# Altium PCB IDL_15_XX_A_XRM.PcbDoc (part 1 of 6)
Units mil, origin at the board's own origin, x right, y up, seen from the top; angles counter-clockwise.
Board outline 6653.34 x 6653.34 mil, 6 copper layers (Top Layer - SIG1, Layer 2 - GND1, Layer 3 - PWR, Layer 4 - PWR, Layer 5 - GND2, Bottom Layer - SIG4), stack 59.843 mil thick; 613 components, 324 nets, 1673 pads, 2316 vias.
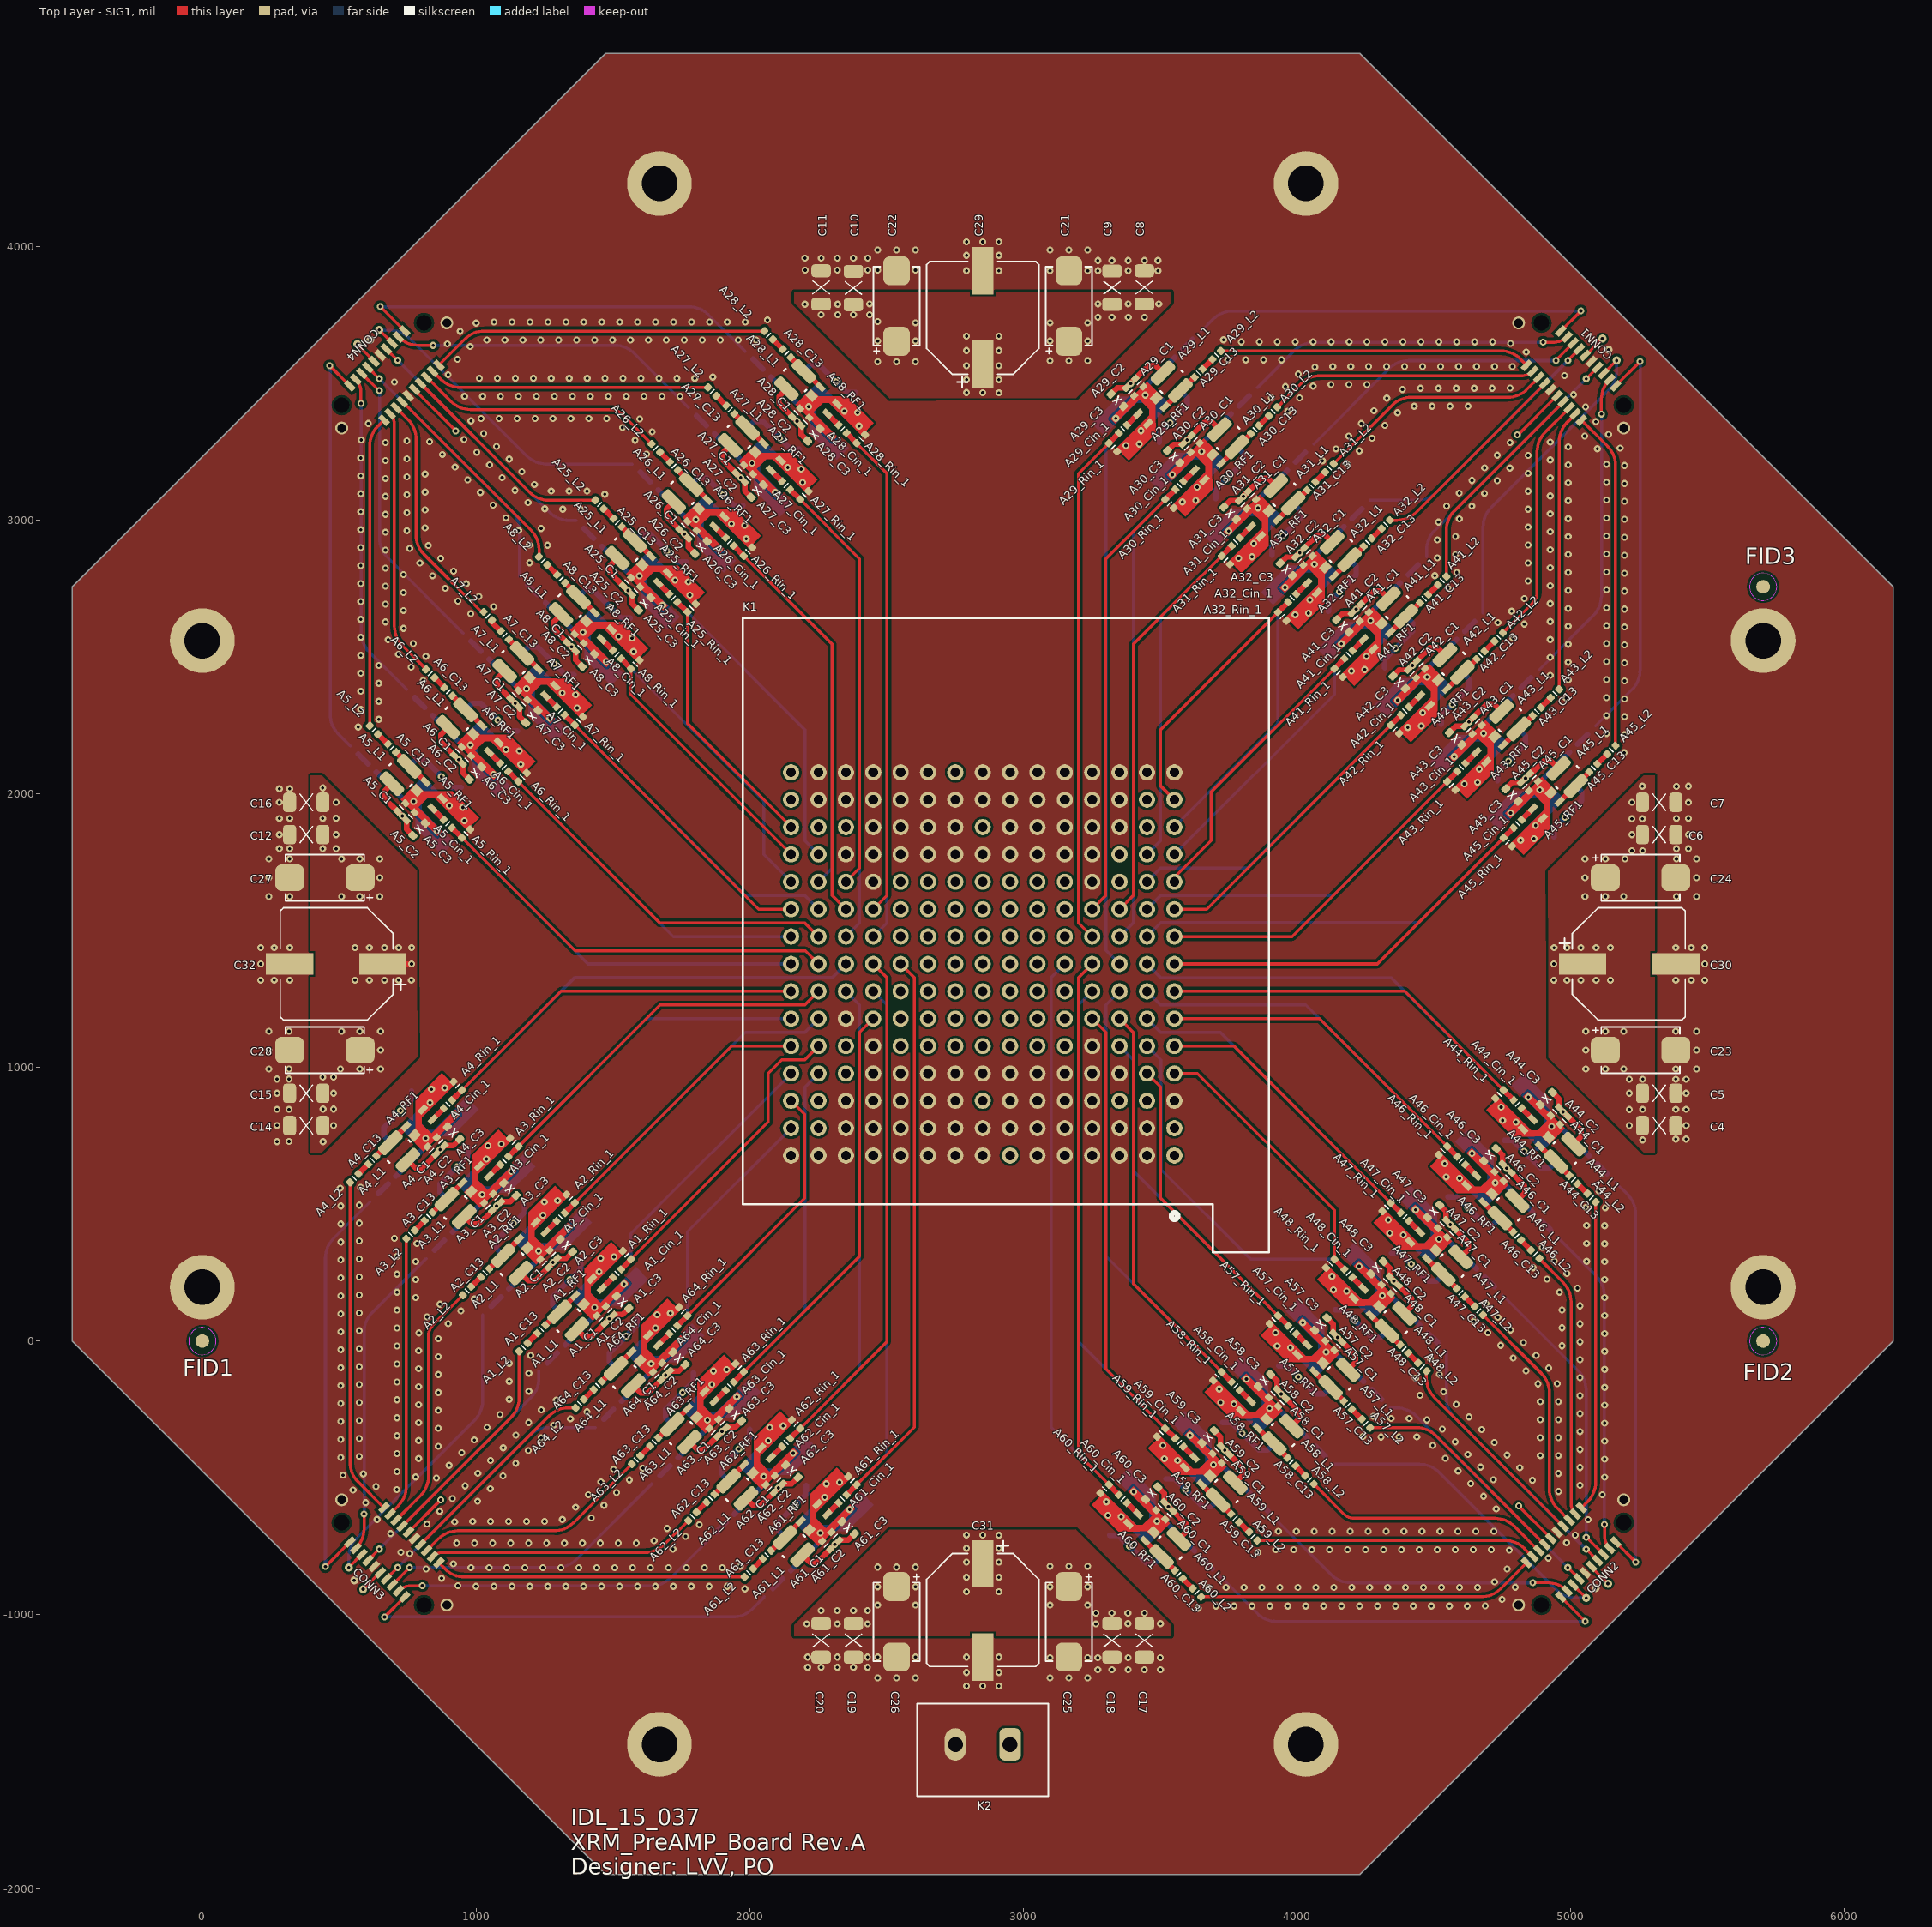
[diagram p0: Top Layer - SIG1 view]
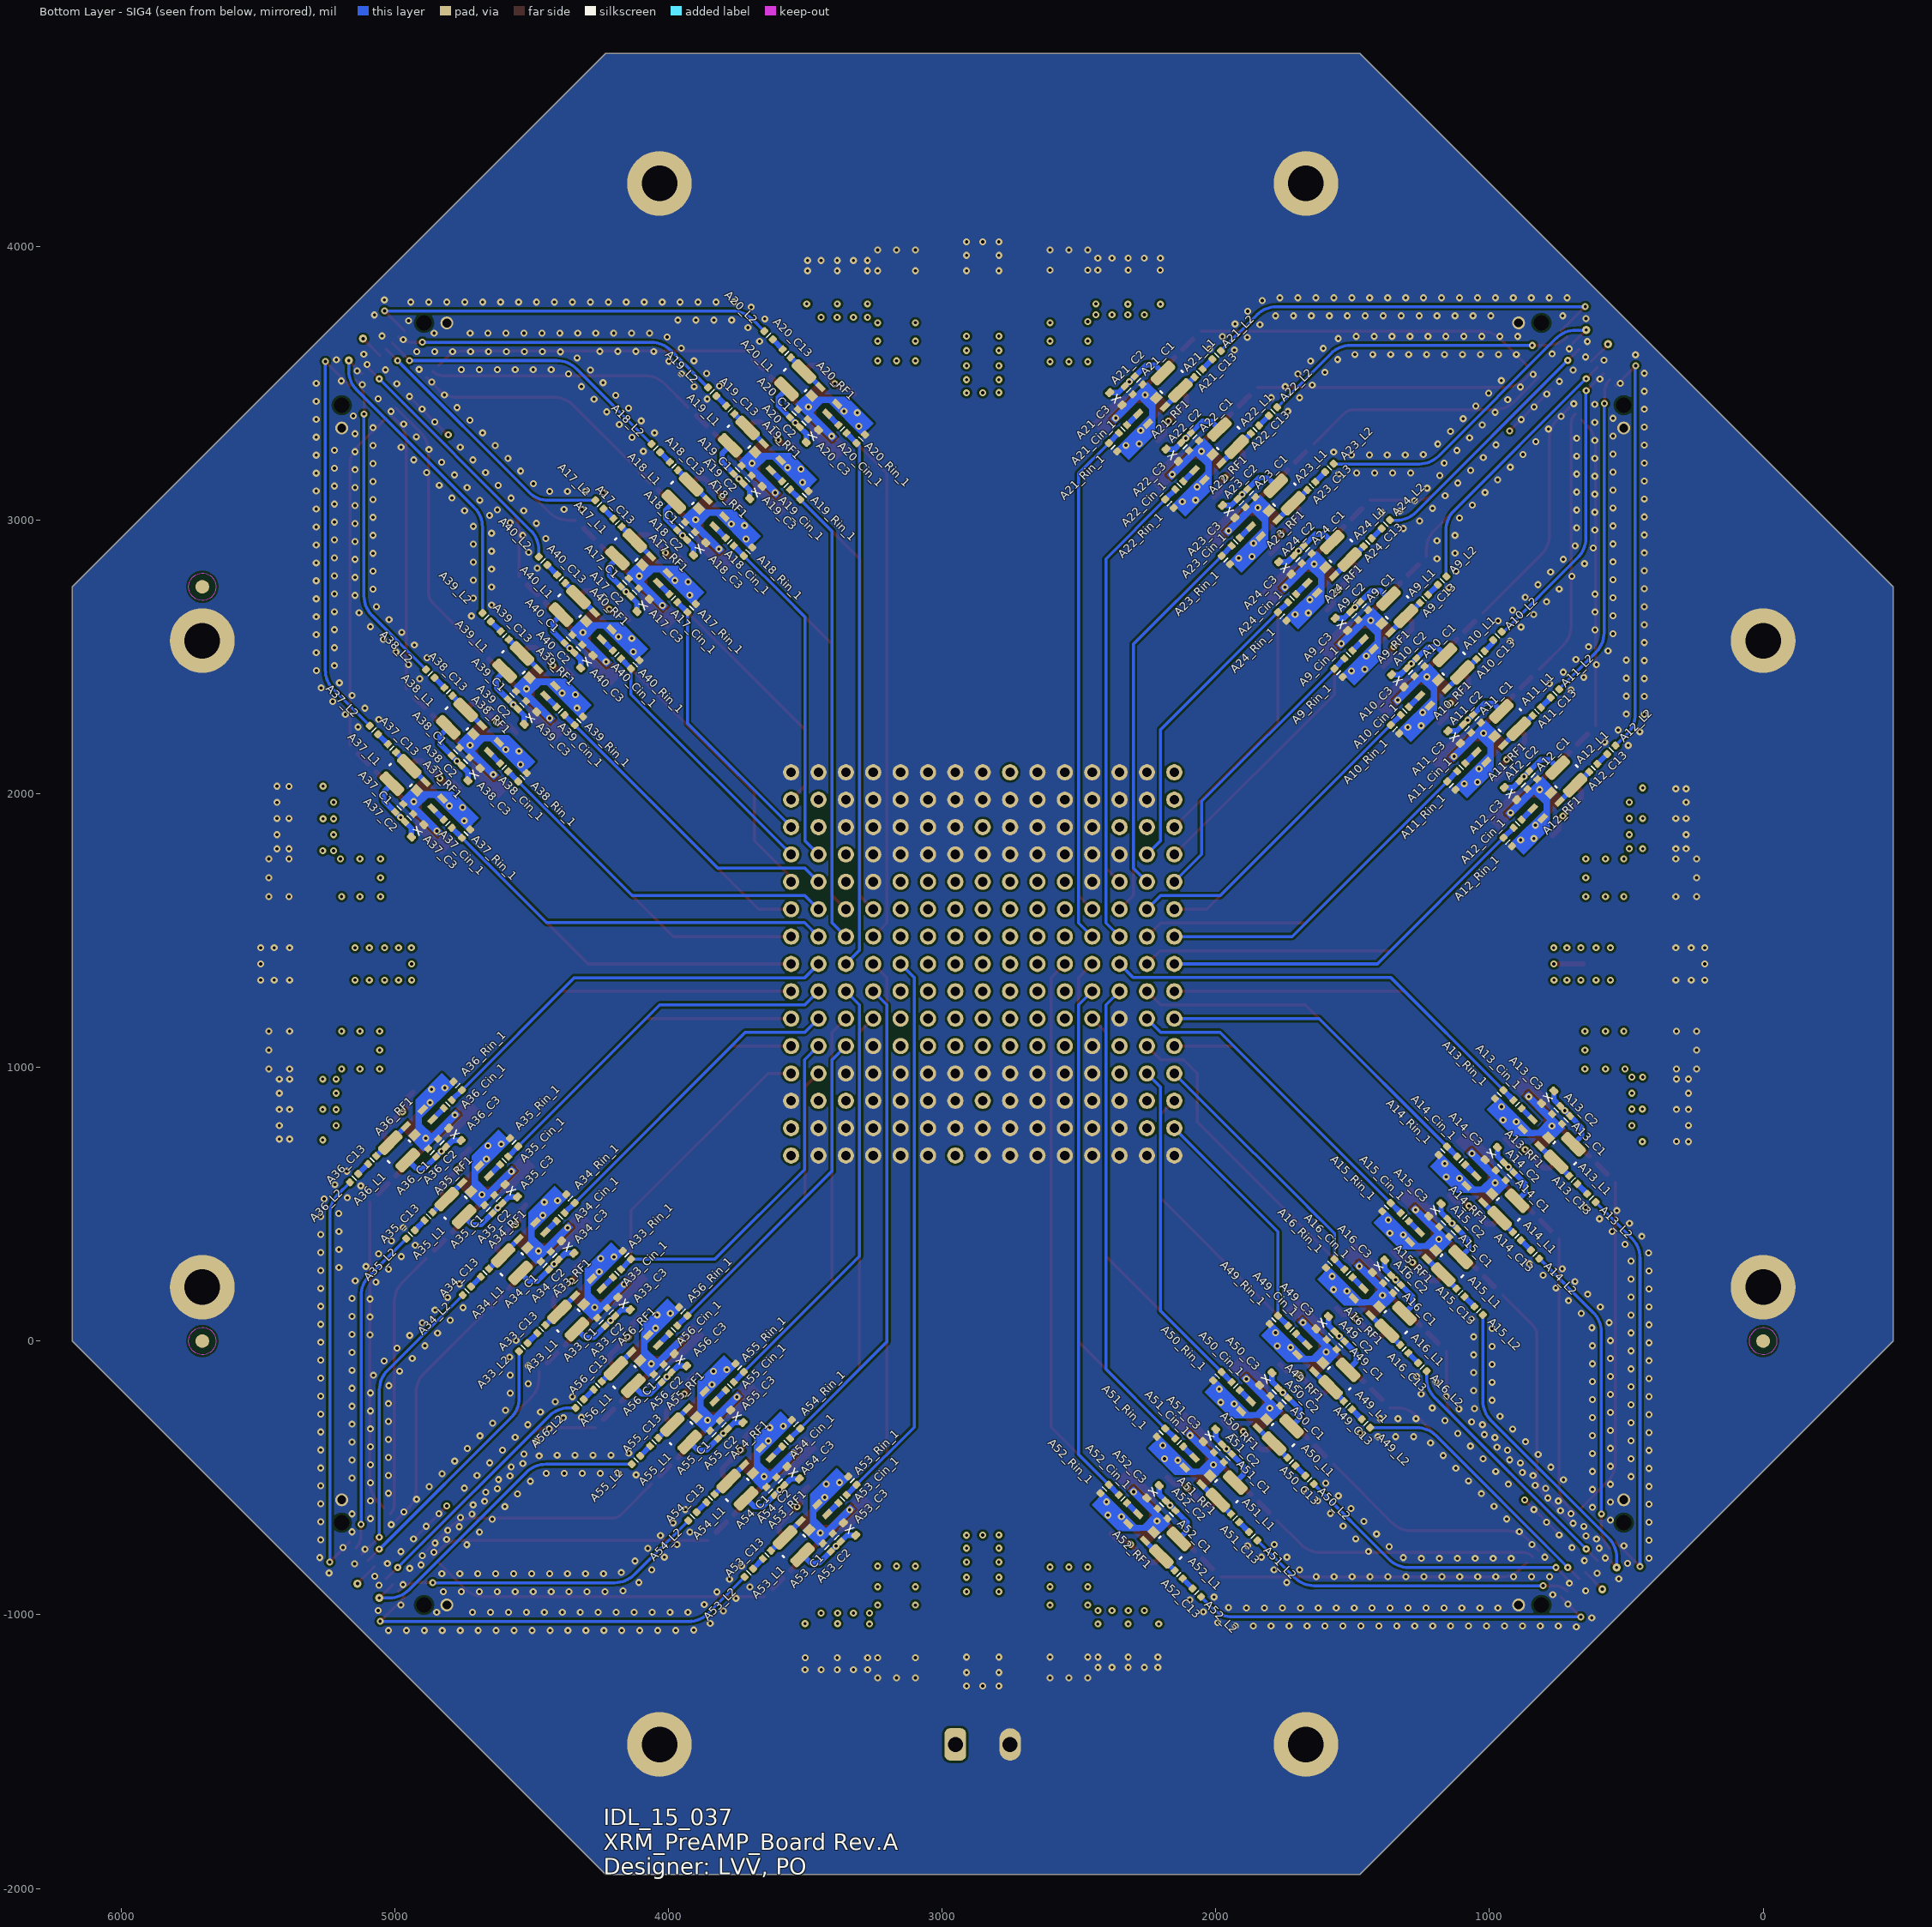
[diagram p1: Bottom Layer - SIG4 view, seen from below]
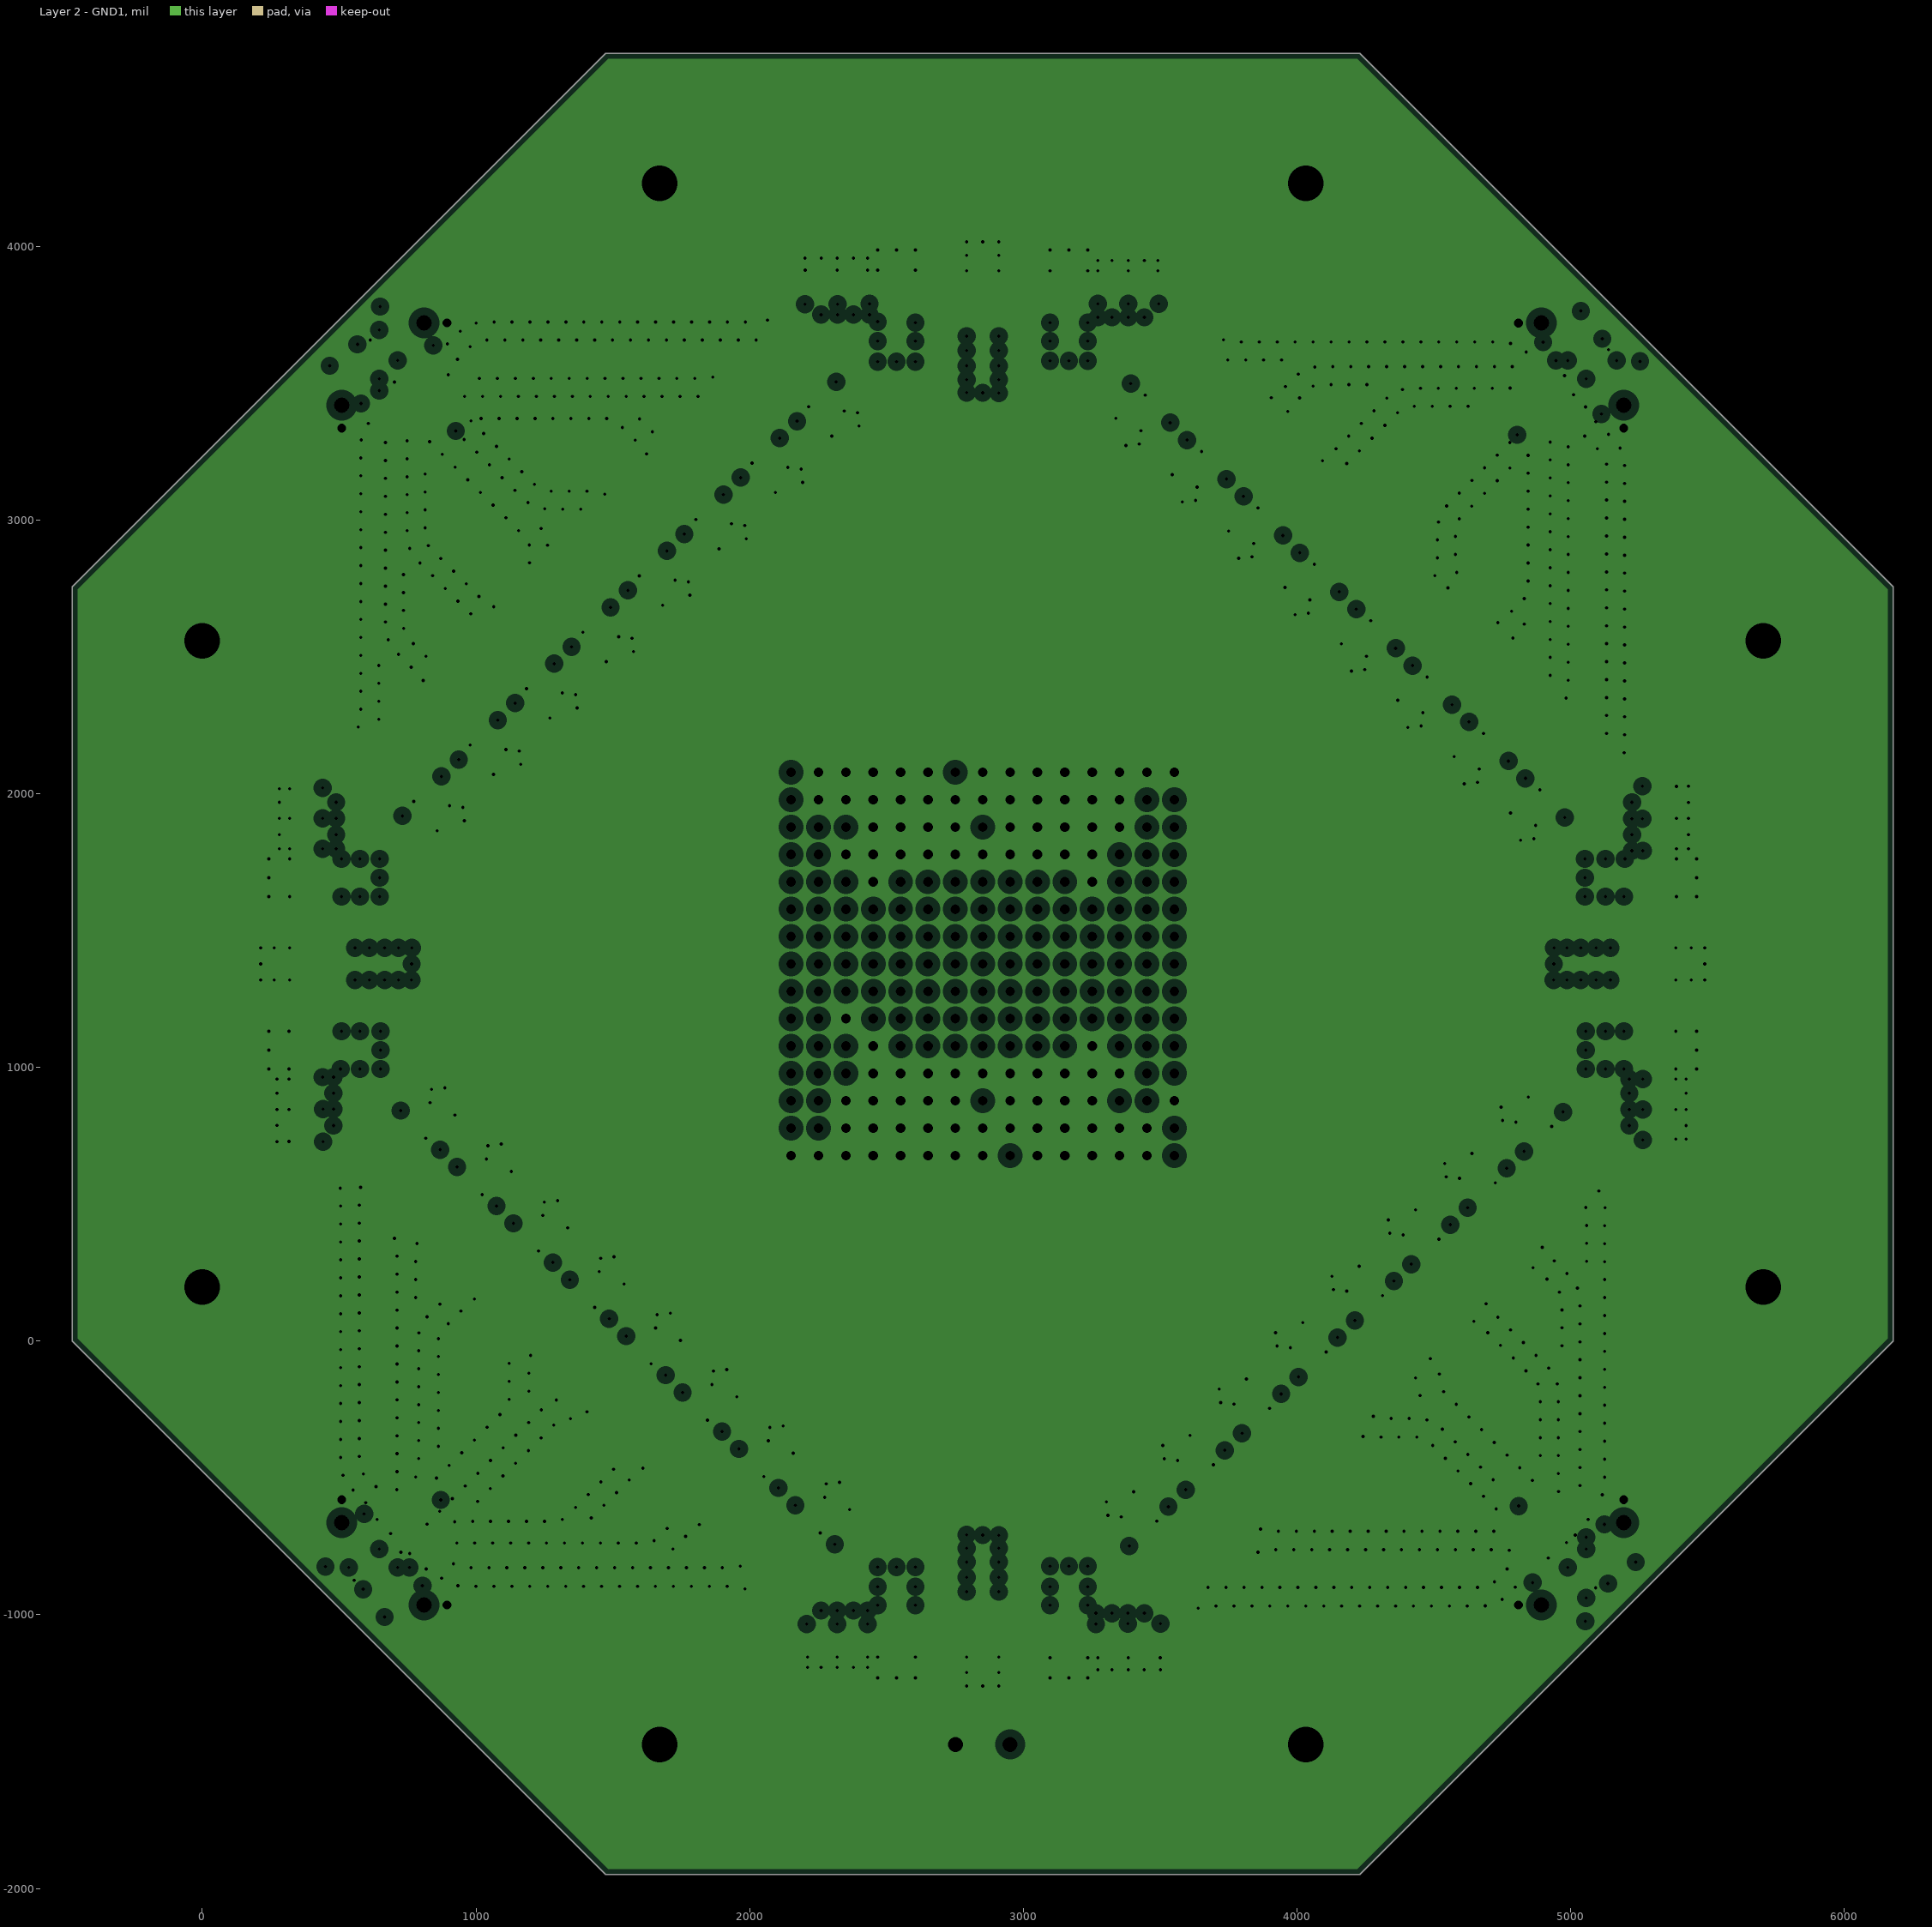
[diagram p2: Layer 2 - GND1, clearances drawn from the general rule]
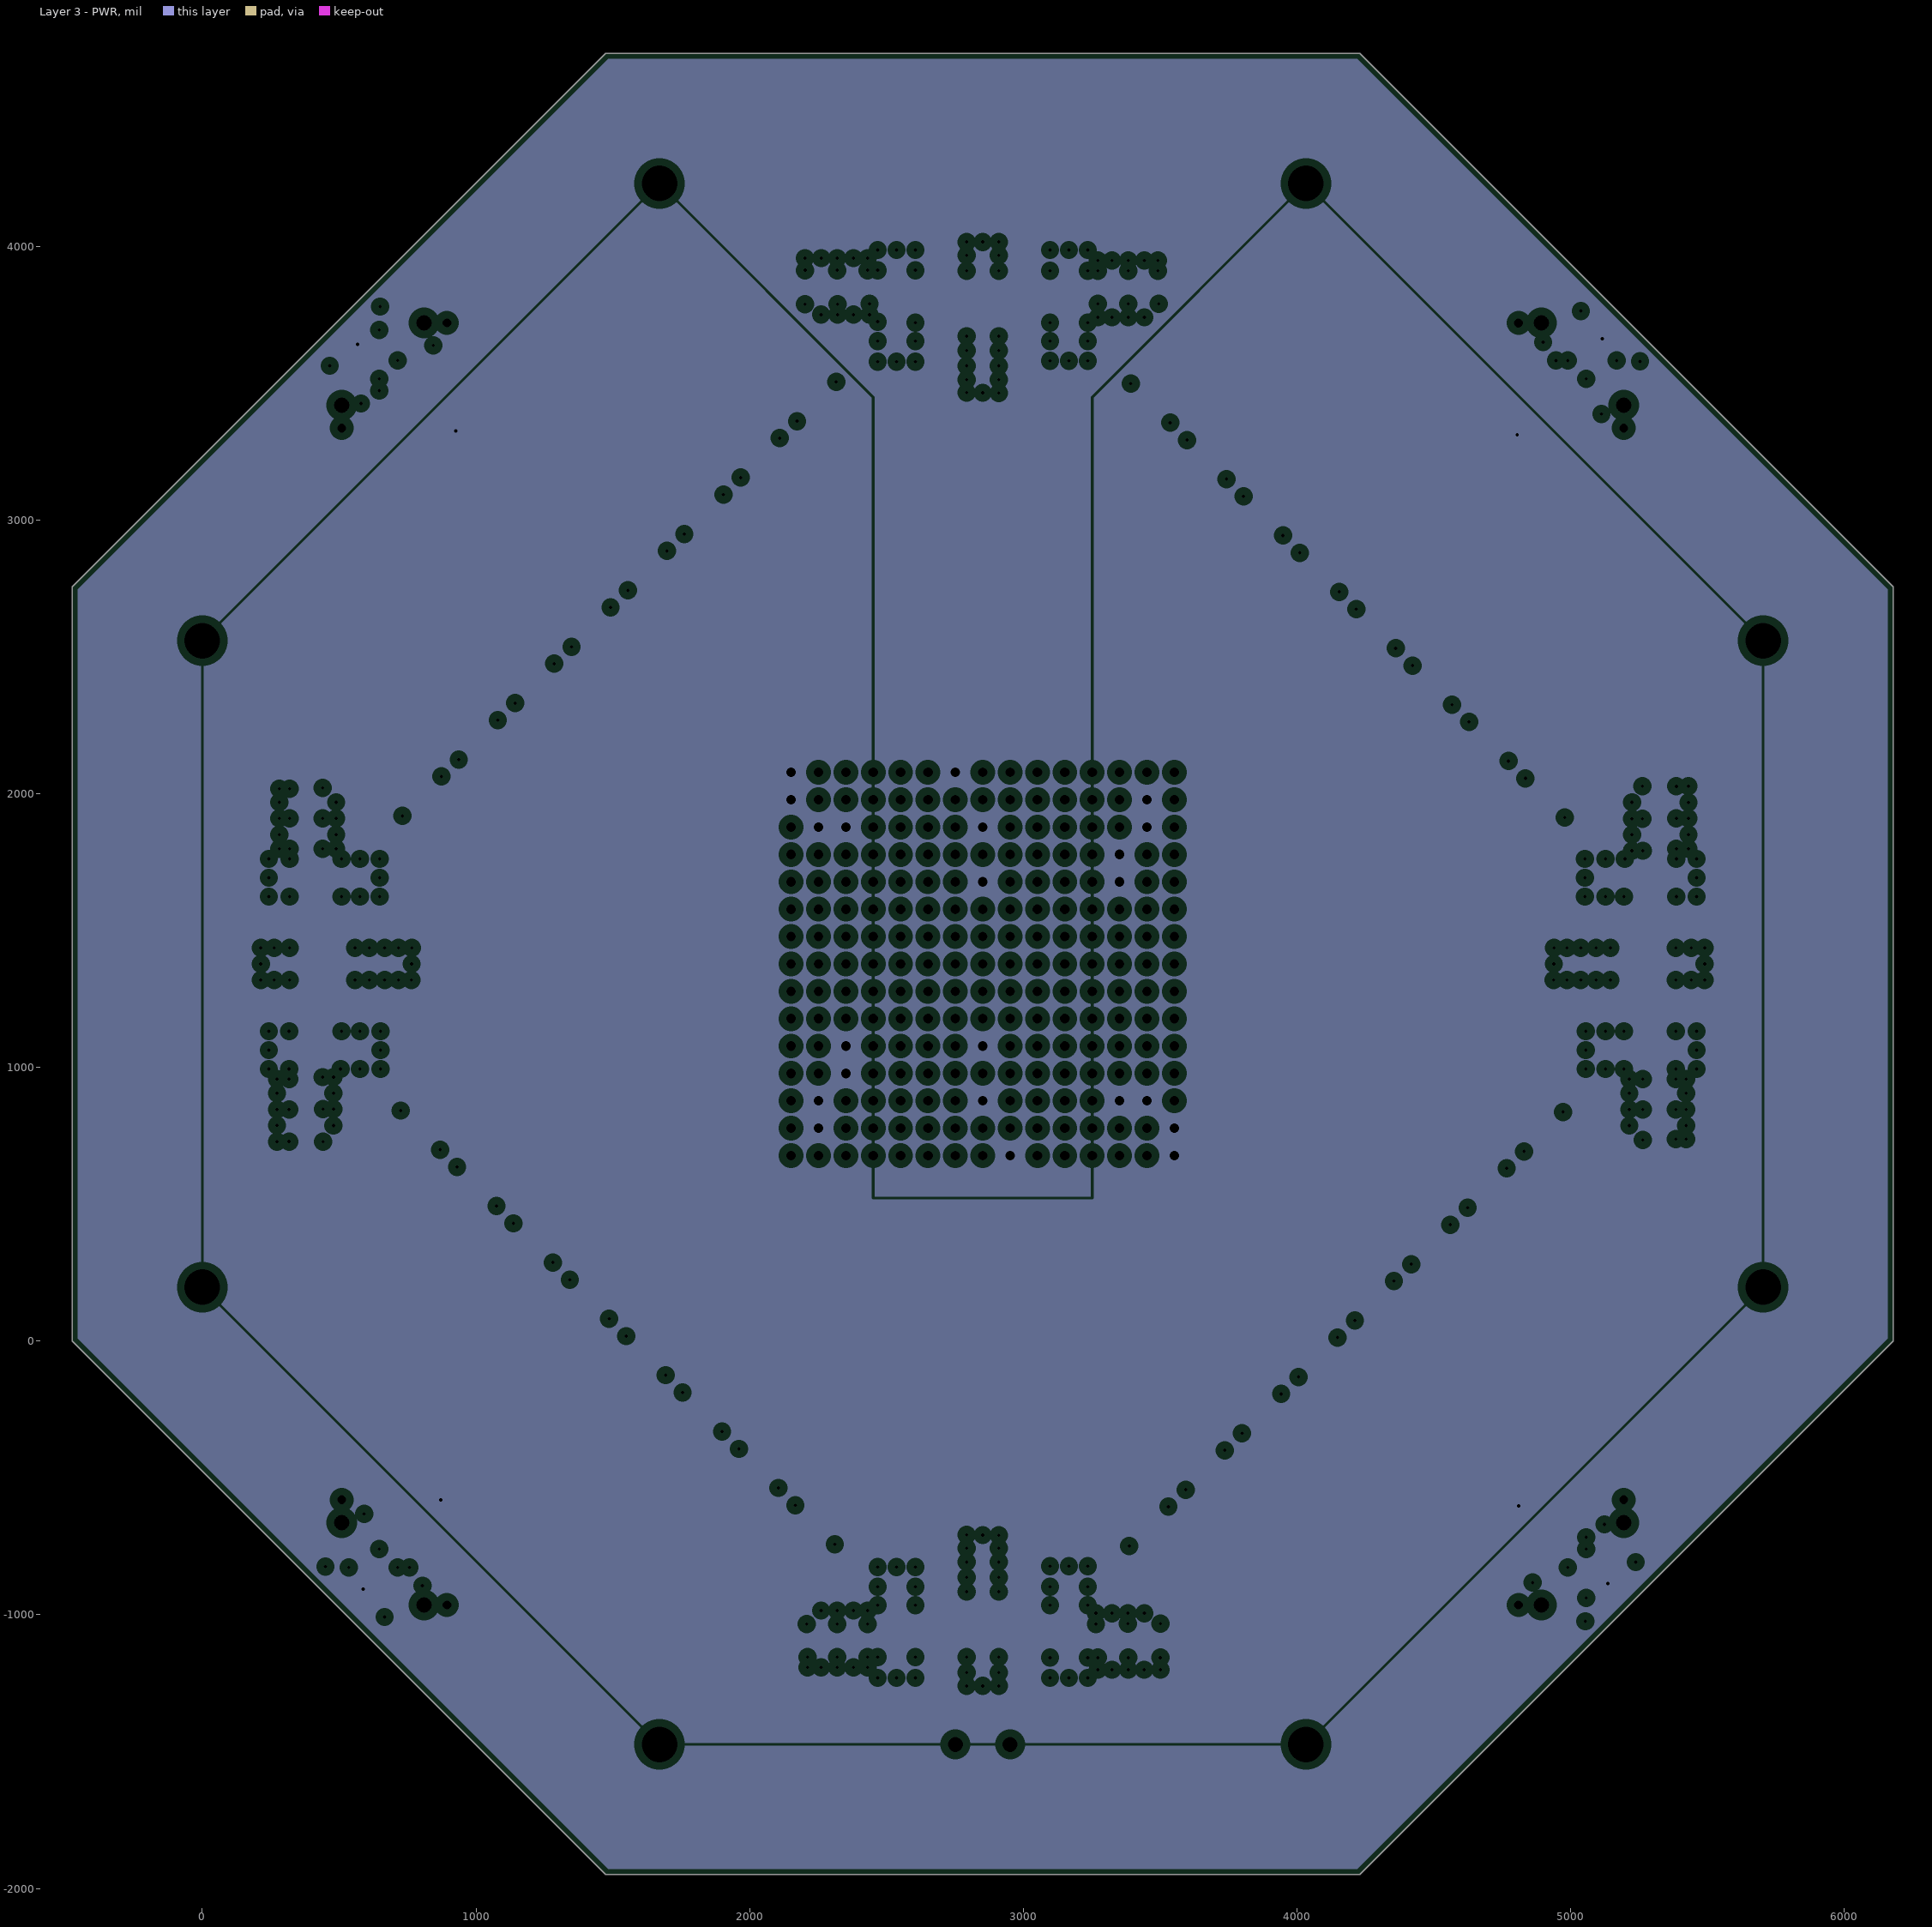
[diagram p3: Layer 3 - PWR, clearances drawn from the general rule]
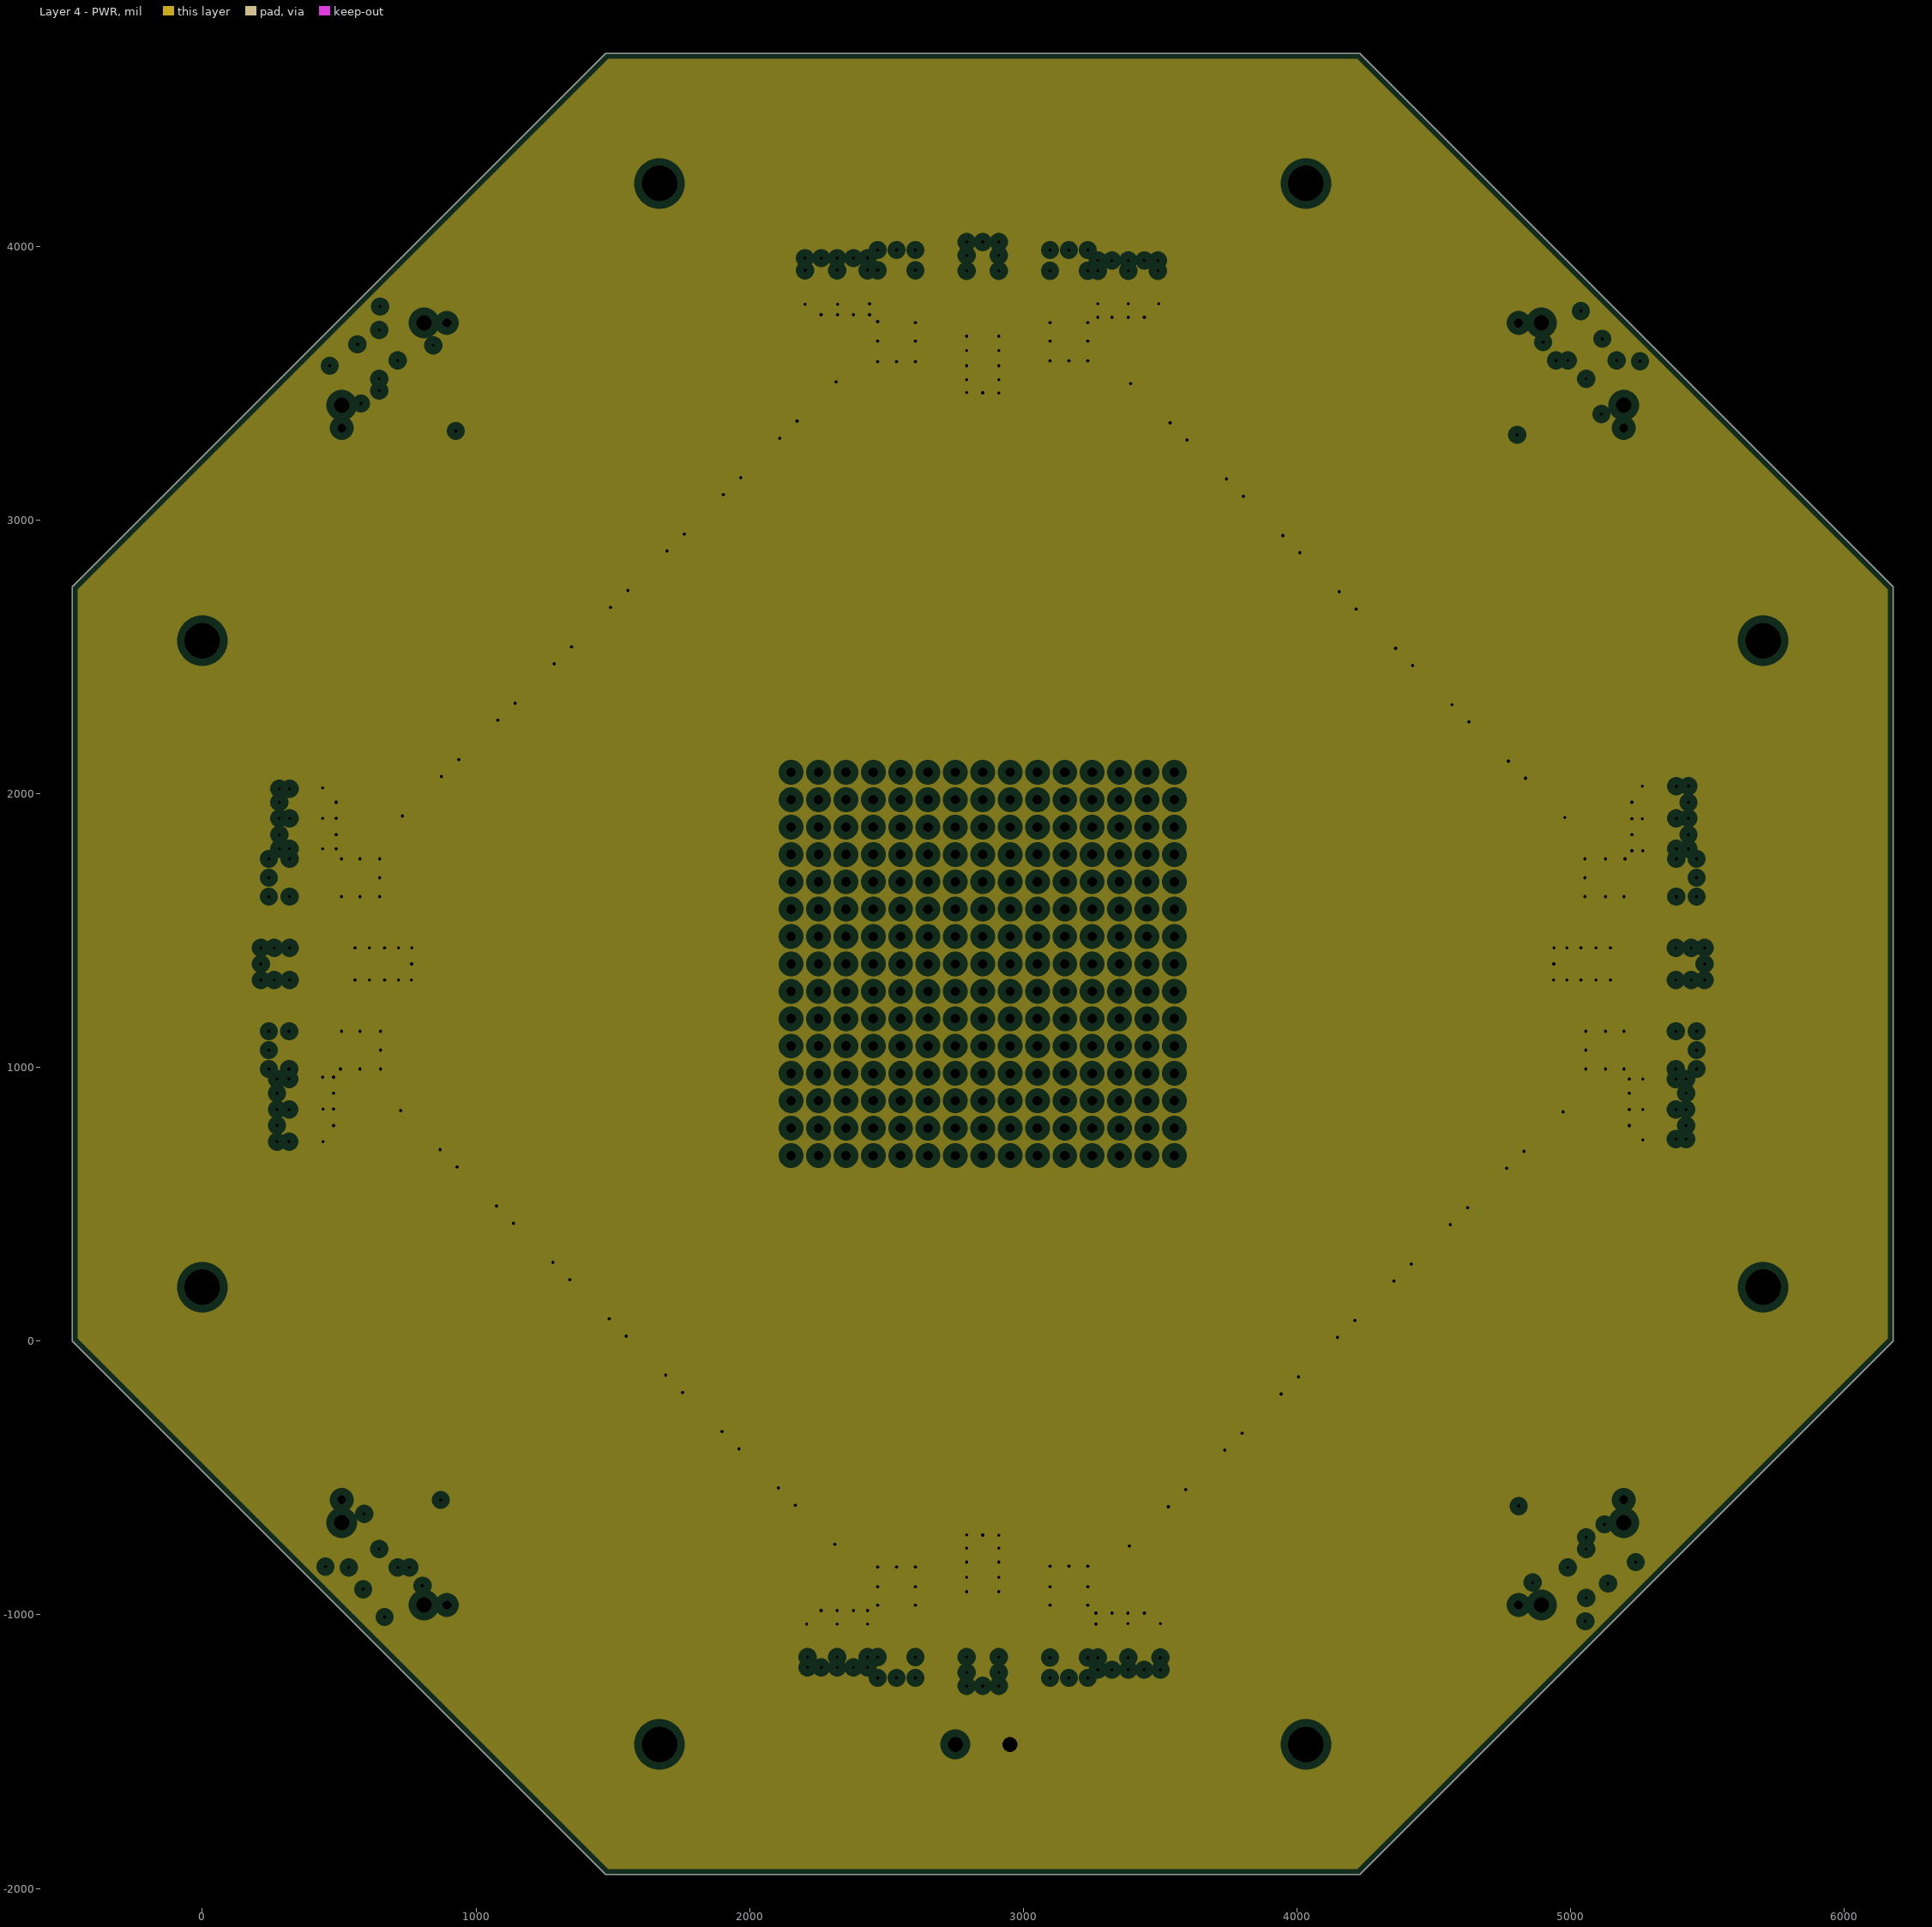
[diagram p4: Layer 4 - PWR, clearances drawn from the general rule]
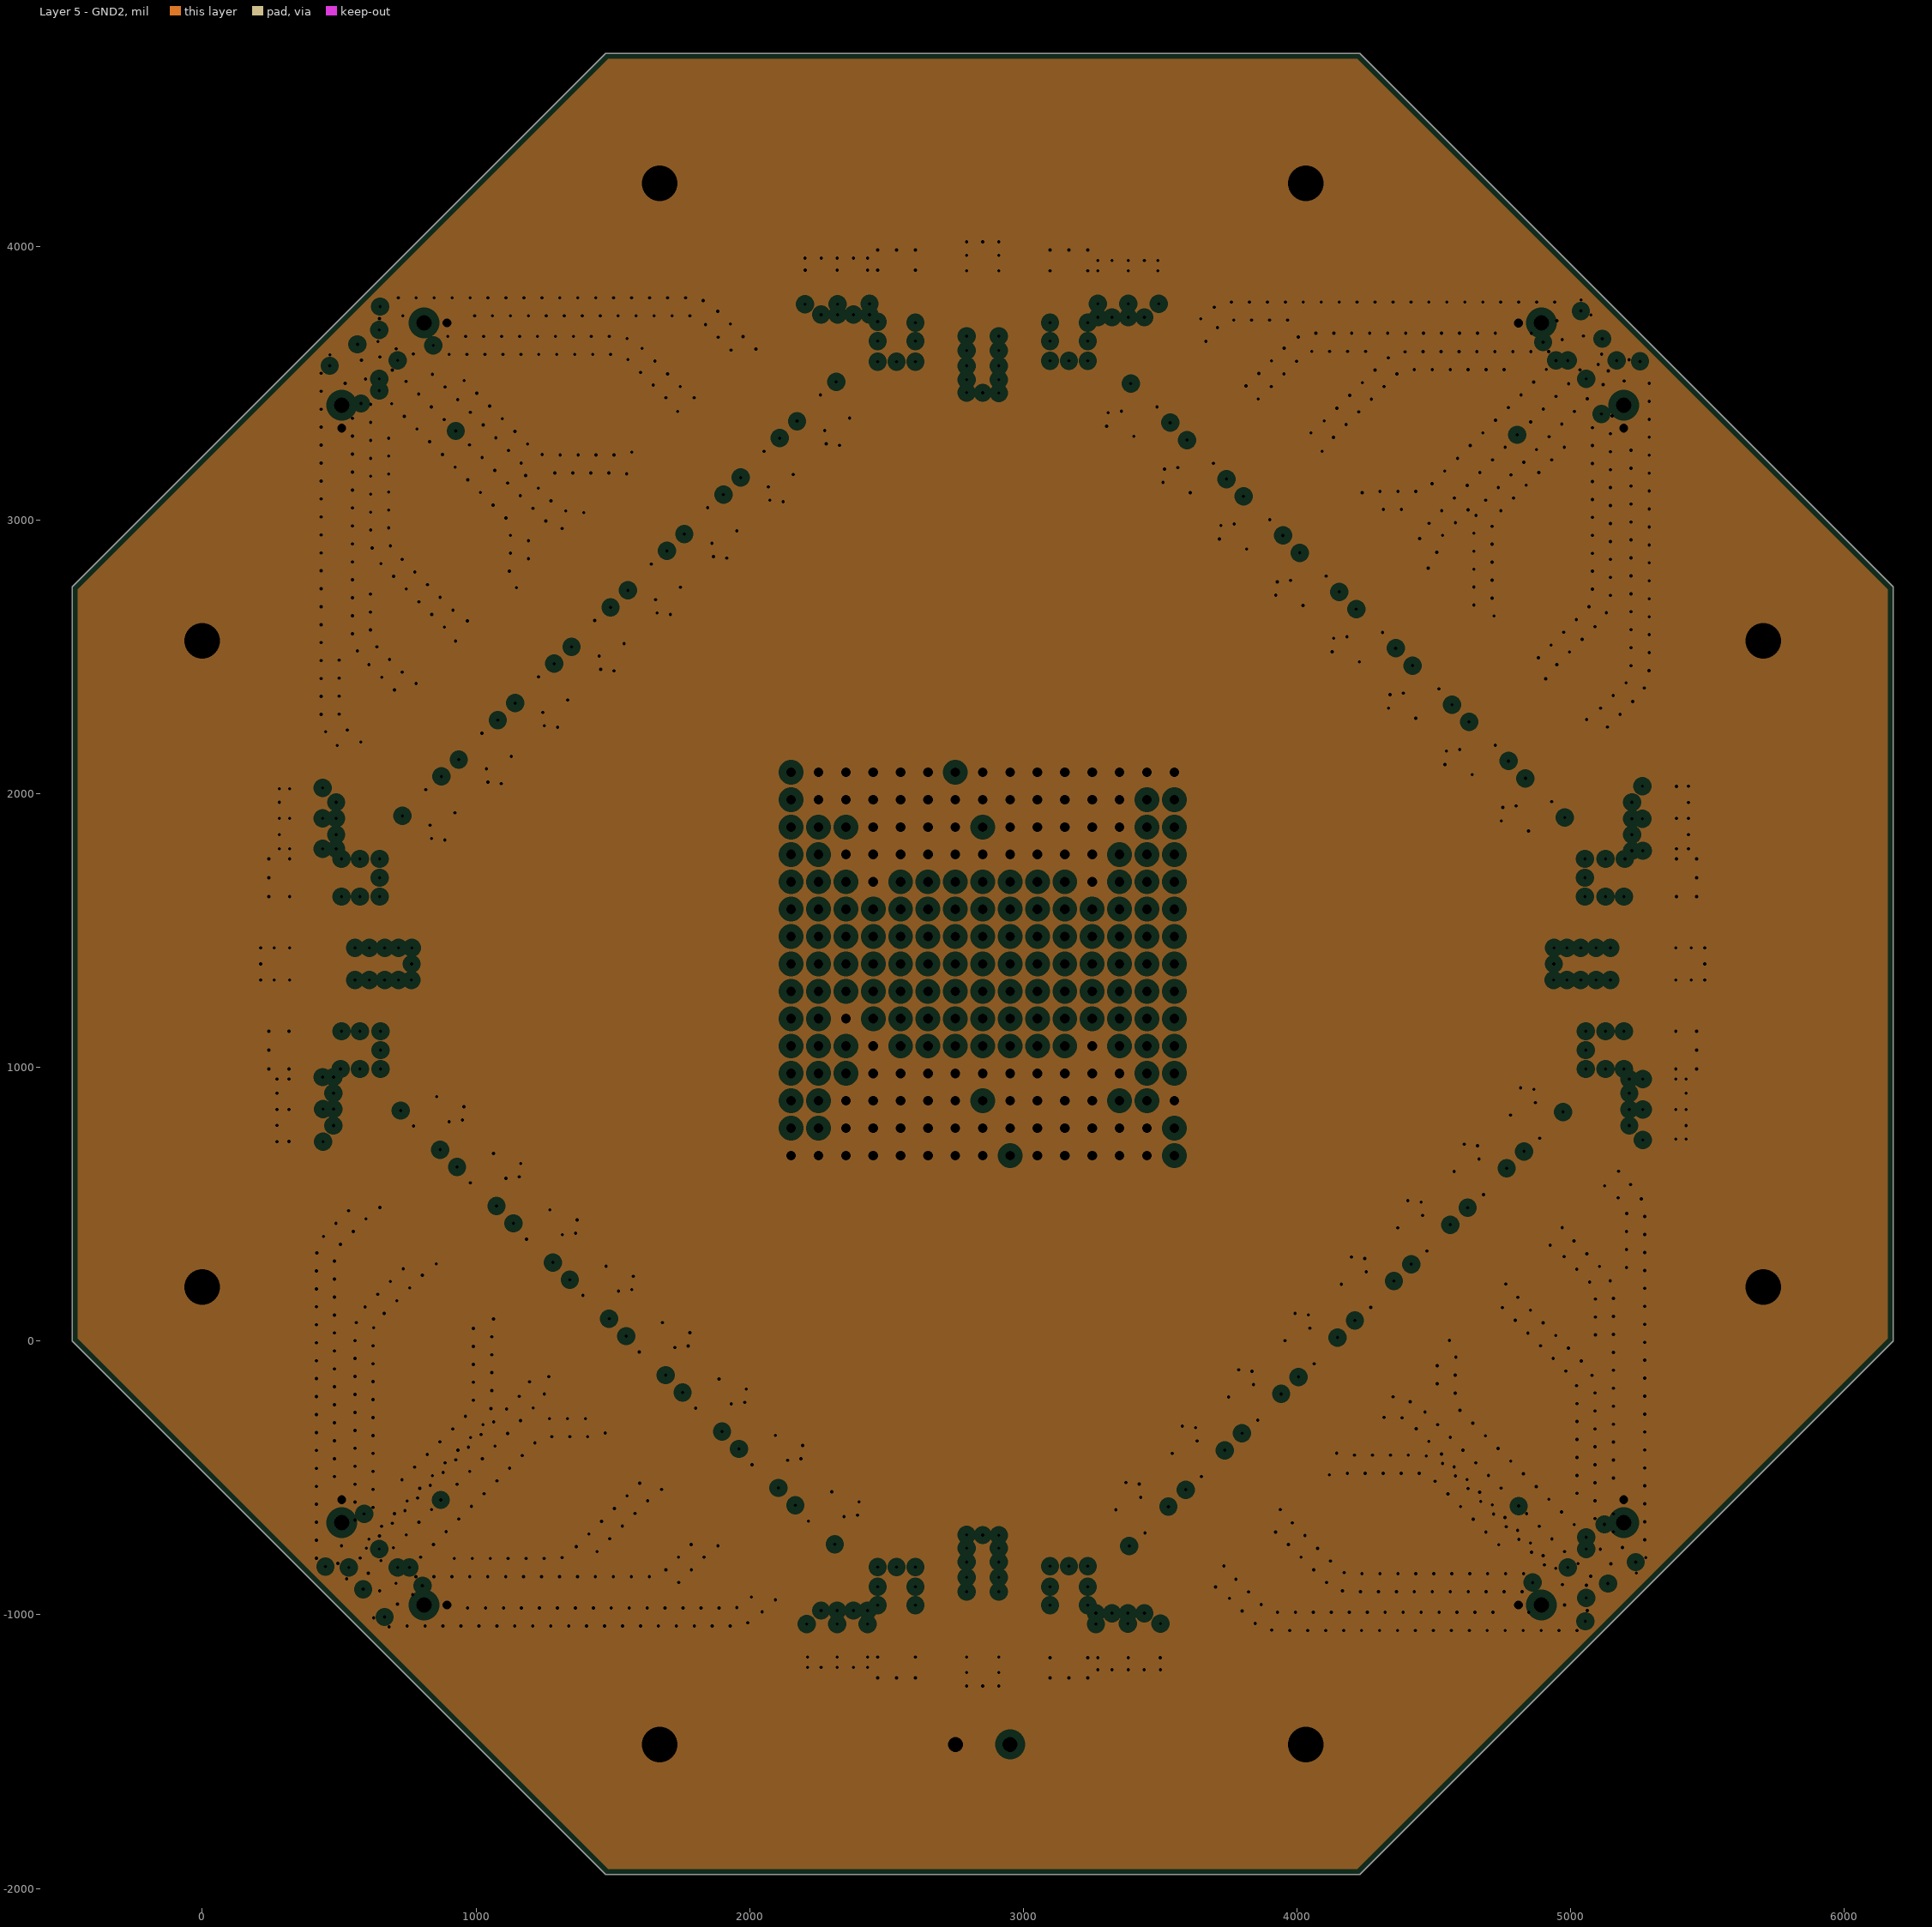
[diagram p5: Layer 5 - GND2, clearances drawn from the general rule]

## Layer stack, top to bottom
Top Solder: solder mask 0.4, Solder Resist, Dk 3.5
Top Layer - SIG1: signal copper 1.378
Dielectric 1: prepreg 5.9055, FR-4, Dk 4.65
Layer 2 - GND1: plane copper 1.378, net GND
Dielectric 3: core 16.9291, FR-4, Dk 4.65
Layer 3 - PWR: plane copper 1.378, net BIAS-VPED
Dielectric 6: prepreg 5.9055, FR-4, Dk 4.65
Layer 4 - PWR: plane copper 1.378, net 3V3
Dielectric 5: core 16.9291, FR-4, Dk 4.65
Layer 5 - GND2: plane copper 1.378, net GND
Dielectric 4: prepreg 5.9055, FR-4, Dk 4.65
Bottom Layer - SIG4: signal copper 1.378
Bottom Solder: solder mask 0.4, Solder Resist, Dk 3.5

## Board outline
1473.48,-1948.72 -475.24,0 -475.24,2755.91 1473.48,4704.63 4229.39,4704.63 6178.11,2755.91 6178.11,0 4229.39,-1948.72

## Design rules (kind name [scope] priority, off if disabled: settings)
AssemblyTestPointUsage [All] p1 off:
AssemblyTestpoint [All] p1 off: testpointundercomponent=TRUE minsize=40 maxsize=100 preferedsize=60 minholesize=0 maxholesize=40 preferedholesize=32 testpointgrid=1 usegrid=TRUE gridtolerance=0.01 allowsidetop=TRUE allowsidebottom=TRUE
Clearance Clearance_Diff [InAnyDifferentialPair  or InNetClass('INPUT') vs InNamedPolygon('L4_5VAN') or InNamedPolygon('L3_5VAP') or InNamedPolygon('L1-GND') OR InNamedPolygon('L6_GND')   or InNamedPolygon('L3_GND') or InNamedPolygon('L4_GND')] p1: gap=15
Clearance Clearance_RF [InNetClass('RF') vs InNamedPolygon('L4_5VAN') or InNamedPolygon('L3_5VAP') or InNamedPolygon('L1-GND') OR InNamedPolygon('L6_GND')   or InNamedPolygon('L3_GND') or InNamedPolygon('L4_GND')] p2: gap=10
Clearance Clearance_Poly [InNamedPolygon('L4_5VAN') or InNamedPolygon('L3_5VAP')  or InNamedPolygon('L1-GND')     OR InNamedPolygon('L6_GND')  or InNamedPolygon('L3_GND') or InNamedPolygon('L4_GND')] p3: gap=8
Clearance Clearance_KeepOut [Iskeepout] p4 off: gap=20
Clearance [All] p5: gap=8
DiffPairsRouting [All] p1: maxlimit=10 minlimit=4.02 mostfreqgap=6 toplayer_minwidth=4.02 toplayer_maxwidth=12.01 toplayer_prefwidth=8 bottomlayer_minwidth=4.02 bottomlayer_maxwidth=12.01 bottomlayer_prefwidth=8 maxuncoupledlength=500
FabricationTestPointUsage [All] p1 off: valid=0 allowmultiple=FALSE
FabricationTestpoint [All] p1 off: side=3 testpointundercomponent=TRUE minsize=40 maxsize=100 preferedsize=60 minholesize=0 maxholesize=40 preferedholesize=32 testpointgrid=1 allowsidetop=TRUE allowsidebottom=TRUE usegrid=TRUE gridtolerance=0.01
Height [All] p1 off: minheight=0 maxheight=1000 prefheight=500
HoleSize [All] p1: absolutevalues=TRUE maxlimit=129.92 minlimit=11.81 maxpercent=80.000 minpercent=20.000
MinimumSolderMaskSliver [All] p1: minsoldermaskwidth=5
PlaneClearance [All] p1: clearance=27.56
PlaneConnect PlaneConnect_vIA [ISvIA] p1: planeconnectstyle=Direct reliefexpansion=20 reliefentries=4 reliefconductorwidth=10 reliefairgap=10
PlaneConnect [All] p2: planeconnectstyle=Direct reliefexpansion=12 reliefentries=4 reliefconductorwidth=15 reliefairgap=8
PolygonConnect PolygonConnect_Via [IsVia or HasFootprint('ChipFET1206-8') or HasFootprint('MAXB2MPCBV') or HasFootprint('MAXB5MPCBV') or HasFootprint('MAXB6MPCBV') or HasFootprint('PINHDR2X20H') or Hasfootprint('PINHDR2X13H')  or HasFootprint('CC1210-X2Y') or HasFootprint('L-COMMCHOKE-4') or HasFootprint('CTC-D7343-43')  or HasFootprint('CC1206N1R ')] p1: connectstyle=Direct reliefconductorwidth=10 reliefentries=4 polygonreliefangle="90 Angle" airgapwidth=10
PolygonConnect PolygonConnect_Main [All] p2: connectstyle=Direct reliefconductorwidth=39.37 reliefentries=4 polygonreliefangle="90 Angle" airgapwidth=10
RoomDefinition U_IDL_15_XX_A_XRM-20_PIN_CONNECTOR [InComponentClass('U_IDL_15_XX_A_XRM-20_PIN_CONNECTOR')] p1: confinementstyle=ConfineIn formatcopy=TRUE lockcomponents=FALSE outline -12830.16,-17167.76 -10830.16,-17167.76 -10830.16,-16167.76 -12830.16,-16167.76
RoomDefinition U_IDL_15_XX_A_XRM(3) [InComponentClass('U_IDL_15_XX_A_XRM(3)')] p2: confinementstyle=ConfineIn formatcopy=TRUE lockcomponents=FALSE outline -12830.16,-17167.76 -10830.16,-17167.76 -10830.16,-16167.76 -12830.16,-16167.76
RoomDefinition IDL_15_XX_A_XRM-TOP(1) [InComponentClass('IDL_15_XX_A_XRM-TOP(1)')] p3: confinementstyle=ConfineIn formatcopy=TRUE lockcomponents=FALSE outline -12830.16,-17167.76 -10830.16,-17167.76 -10830.16,-16167.76 -12830.16,-16167.76
RoomDefinition A64 [InComponentClass('A64')] p4: confinementstyle=ConfineIn formatcopy=TRUE lockcomponents=FALSE outline -12830.16,-17167.76 -10830.16,-17167.76 -10830.16,-16167.76 -12830.16,-16167.76
RoomDefinition A63 [InComponentClass('A63')] p5: confinementstyle=ConfineIn formatcopy=TRUE lockcomponents=FALSE outline -12830.16,-17167.76 -10830.16,-17167.76 -10830.16,-16167.76 -12830.16,-16167.76
RoomDefinition A62 [InComponentClass('A62')] p6: confinementstyle=ConfineIn formatcopy=TRUE lockcomponents=FALSE outline -12830.16,-17167.76 -10830.16,-17167.76 -10830.16,-16167.76 -12830.16,-16167.76
RoomDefinition A61 [InComponentClass('A61')] p7: confinementstyle=ConfineIn formatcopy=TRUE lockcomponents=FALSE outline -12830.16,-17167.76 -10830.16,-17167.76 -10830.16,-16167.76 -12830.16,-16167.76
RoomDefinition A60 [InComponentClass('A60')] p8: confinementstyle=ConfineIn formatcopy=TRUE lockcomponents=FALSE outline -12830.16,-17167.76 -10830.16,-17167.76 -10830.16,-16167.76 -12830.16,-16167.76
RoomDefinition A59 [InComponentClass('A59')] p9: confinementstyle=ConfineIn formatcopy=TRUE lockcomponents=FALSE outline -12830.16,-17167.76 -10830.16,-17167.76 -10830.16,-16167.76 -12830.16,-16167.76
RoomDefinition A58 [InComponentClass('A58')] p10: confinementstyle=ConfineIn formatcopy=TRUE lockcomponents=FALSE outline -12830.16,-17167.76 -10830.16,-17167.76 -10830.16,-16167.76 -12830.16,-16167.76
RoomDefinition A57 [InComponentClass('A57')] p11: confinementstyle=ConfineIn formatcopy=TRUE lockcomponents=FALSE outline -12830.16,-17167.76 -10830.16,-17167.76 -10830.16,-16167.76 -12830.16,-16167.76
RoomDefinition A56 [InComponentClass('A56')] p12: confinementstyle=ConfineIn formatcopy=TRUE lockcomponents=FALSE outline -12830.16,-17167.76 -10830.16,-17167.76 -10830.16,-16167.76 -12830.16,-16167.76
RoomDefinition A55 [InComponentClass('A55')] p13: confinementstyle=ConfineIn formatcopy=TRUE lockcomponents=FALSE outline -12830.16,-17167.76 -10830.16,-17167.76 -10830.16,-16167.76 -12830.16,-16167.76
RoomDefinition A54 [InComponentClass('A54')] p14: confinementstyle=ConfineIn formatcopy=TRUE lockcomponents=FALSE outline -12830.16,-17167.76 -10830.16,-17167.76 -10830.16,-16167.76 -12830.16,-16167.76
RoomDefinition A53 [InComponentClass('A53')] p15: confinementstyle=ConfineIn formatcopy=TRUE lockcomponents=FALSE outline -12830.16,-17167.76 -10830.16,-17167.76 -10830.16,-16167.76 -12830.16,-16167.76
RoomDefinition A52 [InComponentClass('A52')] p16: confinementstyle=ConfineIn formatcopy=TRUE lockcomponents=FALSE outline -12830.16,-17167.76 -10830.16,-17167.76 -10830.16,-16167.76 -12830.16,-16167.76
RoomDefinition A51 [InComponentClass('A51')] p17: confinementstyle=ConfineIn formatcopy=TRUE lockcomponents=FALSE outline -12830.16,-17167.76 -10830.16,-17167.76 -10830.16,-16167.76 -12830.16,-16167.76
RoomDefinition A50 [InComponentClass('A50')] p18: confinementstyle=ConfineIn formatcopy=TRUE lockcomponents=FALSE outline -12830.16,-17167.76 -10830.16,-17167.76 -10830.16,-16167.76 -12830.16,-16167.76
RoomDefinition A49 [InComponentClass('A49')] p19: confinementstyle=ConfineIn formatcopy=TRUE lockcomponents=FALSE outline -12830.16,-17167.76 -10830.16,-17167.76 -10830.16,-16167.76 -12830.16,-16167.76
RoomDefinition A48 [InComponentClass('A48')] p20: confinementstyle=ConfineIn formatcopy=TRUE lockcomponents=FALSE outline -12830.16,-17167.76 -10830.16,-17167.76 -10830.16,-16167.76 -12830.16,-16167.76
RoomDefinition A47 [InComponentClass('A47')] p21: confinementstyle=ConfineIn formatcopy=TRUE lockcomponents=FALSE outline -12830.16,-17167.76 -10830.16,-17167.76 -10830.16,-16167.76 -12830.16,-16167.76
RoomDefinition A46 [InComponentClass('A46')] p22: confinementstyle=ConfineIn formatcopy=TRUE lockcomponents=FALSE outline -12830.16,-17167.76 -10830.16,-17167.76 -10830.16,-16167.76 -12830.16,-16167.76
RoomDefinition A45 [InComponentClass('A45')] p23: confinementstyle=ConfineIn formatcopy=TRUE lockcomponents=FALSE outline -12830.16,-17167.76 -10830.16,-17167.76 -10830.16,-16167.76 -12830.16,-16167.76
RoomDefinition A44 [InComponentClass('A44')] p24: confinementstyle=ConfineIn formatcopy=TRUE lockcomponents=FALSE outline -12830.16,-17167.76 -10830.16,-17167.76 -10830.16,-16167.76 -12830.16,-16167.76
RoomDefinition A43 [InComponentClass('A43')] p25: confinementstyle=ConfineIn formatcopy=TRUE lockcomponents=FALSE outline -12830.16,-17167.76 -10830.16,-17167.76 -10830.16,-16167.76 -12830.16,-16167.76
RoomDefinition A42 [InComponentClass('A42')] p26: confinementstyle=ConfineIn formatcopy=TRUE lockcomponents=FALSE outline -12830.16,-17167.76 -10830.16,-17167.76 -10830.16,-16167.76 -12830.16,-16167.76
RoomDefinition A41 [InComponentClass('A41')] p27: confinementstyle=ConfineIn formatcopy=TRUE lockcomponents=FALSE outline -12830.16,-17167.76 -10830.16,-17167.76 -10830.16,-16167.76 -12830.16,-16167.76
RoomDefinition A40 [InComponentClass('A40')] p28: confinementstyle=ConfineIn formatcopy=TRUE lockcomponents=FALSE outline -12830.16,-17167.76 -10830.16,-17167.76 -10830.16,-16167.76 -12830.16,-16167.76
RoomDefinition A39 [InComponentClass('A39')] p29: confinementstyle=ConfineIn formatcopy=TRUE lockcomponents=FALSE outline -12830.16,-17167.76 -10830.16,-17167.76 -10830.16,-16167.76 -12830.16,-16167.76
RoomDefinition A38 [InComponentClass('A38')] p30: confinementstyle=ConfineIn formatcopy=TRUE lockcomponents=FALSE outline -12830.16,-17167.76 -10830.16,-17167.76 -10830.16,-16167.76 -12830.16,-16167.76
RoomDefinition A37 [InComponentClass('A37')] p31: confinementstyle=ConfineIn formatcopy=TRUE lockcomponents=FALSE outline -12830.16,-17167.76 -10830.16,-17167.76 -10830.16,-16167.76 -12830.16,-16167.76
RoomDefinition A36 [InComponentClass('A36')] p32: confinementstyle=ConfineIn formatcopy=TRUE lockcomponents=FALSE outline -12830.16,-17167.76 -10830.16,-17167.76 -10830.16,-16167.76 -12830.16,-16167.76
RoomDefinition A35 [InComponentClass('A35')] p33: confinementstyle=ConfineIn formatcopy=TRUE lockcomponents=FALSE outline -12830.16,-17167.76 -10830.16,-17167.76 -10830.16,-16167.76 -12830.16,-16167.76
RoomDefinition A34 [InComponentClass('A34')] p34: confinementstyle=ConfineIn formatcopy=TRUE lockcomponents=FALSE outline -12830.16,-17167.76 -10830.16,-17167.76 -10830.16,-16167.76 -12830.16,-16167.76
RoomDefinition A33 [InComponentClass('A33')] p35: confinementstyle=ConfineIn formatcopy=TRUE lockcomponents=FALSE outline -12830.16,-17167.76 -10830.16,-17167.76 -10830.16,-16167.76 -12830.16,-16167.76
RoomDefinition A32 [InComponentClass('A32')] p36: confinementstyle=ConfineIn formatcopy=TRUE lockcomponents=FALSE outline -12830.16,-17167.76 -10830.16,-17167.76 -10830.16,-16167.76 -12830.16,-16167.76
RoomDefinition A31 [InComponentClass('A31')] p37: confinementstyle=ConfineIn formatcopy=TRUE lockcomponents=FALSE outline -12830.16,-17167.76 -10830.16,-17167.76 -10830.16,-16167.76 -12830.16,-16167.76
RoomDefinition A30 [InComponentClass('A30')] p38: confinementstyle=ConfineIn formatcopy=TRUE lockcomponents=FALSE outline -12830.16,-17167.76 -10830.16,-17167.76 -10830.16,-16167.76 -12830.16,-16167.76
RoomDefinition A29 [InComponentClass('A29')] p39: confinementstyle=ConfineIn formatcopy=TRUE lockcomponents=FALSE outline -12830.16,-17167.76 -10830.16,-17167.76 -10830.16,-16167.76 -12830.16,-16167.76
RoomDefinition A28 [InComponentClass('A28')] p40: confinementstyle=ConfineIn formatcopy=TRUE lockcomponents=FALSE outline -12830.16,-17167.76 -10830.16,-17167.76 -10830.16,-16167.76 -12830.16,-16167.76
RoomDefinition A27 [InComponentClass('A27')] p41: confinementstyle=ConfineIn formatcopy=TRUE lockcomponents=FALSE outline -12830.16,-17167.76 -10830.16,-17167.76 -10830.16,-16167.76 -12830.16,-16167.76
RoomDefinition A26 [InComponentClass('A26')] p42: confinementstyle=ConfineIn formatcopy=TRUE lockcomponents=FALSE outline -12830.16,-17167.76 -10830.16,-17167.76 -10830.16,-16167.76 -12830.16,-16167.76
RoomDefinition A25 [InComponentClass('A25')] p43: confinementstyle=ConfineIn formatcopy=TRUE lockcomponents=FALSE outline -12830.16,-17167.76 -10830.16,-17167.76 -10830.16,-16167.76 -12830.16,-16167.76
RoomDefinition A24 [InComponentClass('A24')] p44: confinementstyle=ConfineIn formatcopy=TRUE lockcomponents=FALSE outline -12830.16,-17167.76 -10830.16,-17167.76 -10830.16,-16167.76 -12830.16,-16167.76
RoomDefinition A23 [InComponentClass('A23')] p45: confinementstyle=ConfineIn formatcopy=TRUE lockcomponents=FALSE outline -12830.16,-17167.76 -10830.16,-17167.76 -10830.16,-16167.76 -12830.16,-16167.76
RoomDefinition A22 [InComponentClass('A22')] p46: confinementstyle=ConfineIn formatcopy=TRUE lockcomponents=FALSE outline -12830.16,-17167.76 -10830.16,-17167.76 -10830.16,-16167.76 -12830.16,-16167.76
RoomDefinition A21 [InComponentClass('A21')] p47: confinementstyle=ConfineIn formatcopy=TRUE lockcomponents=FALSE outline -12830.16,-17167.76 -10830.16,-17167.76 -10830.16,-16167.76 -12830.16,-16167.76
RoomDefinition A20 [InComponentClass('A20')] p48: confinementstyle=ConfineIn formatcopy=TRUE lockcomponents=FALSE outline -12830.16,-17167.76 -10830.16,-17167.76 -10830.16,-16167.76 -12830.16,-16167.76
RoomDefinition A19 [InComponentClass('A19')] p49: confinementstyle=ConfineIn formatcopy=TRUE lockcomponents=FALSE outline -12830.16,-17167.76 -10830.16,-17167.76 -10830.16,-16167.76 -12830.16,-16167.76
RoomDefinition A18 [InComponentClass('A18')] p50: confinementstyle=ConfineIn formatcopy=TRUE lockcomponents=FALSE outline -12830.16,-17167.76 -10830.16,-17167.76 -10830.16,-16167.76 -12830.16,-16167.76
RoomDefinition A17 [InComponentClass('A17')] p51: confinementstyle=ConfineIn formatcopy=TRUE lockcomponents=FALSE outline -12830.16,-17167.76 -10830.16,-17167.76 -10830.16,-16167.76 -12830.16,-16167.76
RoomDefinition A16 [InComponentClass('A16')] p52: confinementstyle=ConfineIn formatcopy=TRUE lockcomponents=FALSE outline -12830.16,-17167.76 -10830.16,-17167.76 -10830.16,-16167.76 -12830.16,-16167.76
RoomDefinition A15 [InComponentClass('A15')] p53: confinementstyle=ConfineIn formatcopy=TRUE lockcomponents=FALSE outline -12830.16,-17167.76 -10830.16,-17167.76 -10830.16,-16167.76 -12830.16,-16167.76
RoomDefinition A14 [InComponentClass('A14')] p54: confinementstyle=ConfineIn formatcopy=TRUE lockcomponents=FALSE outline -12830.16,-17167.76 -10830.16,-17167.76 -10830.16,-16167.76 -12830.16,-16167.76
RoomDefinition A13 [InComponentClass('A13')] p55: confinementstyle=ConfineIn formatcopy=TRUE lockcomponents=FALSE outline -12830.16,-17167.76 -10830.16,-17167.76 -10830.16,-16167.76 -12830.16,-16167.76
RoomDefinition A12 [InComponentClass('A12')] p56: confinementstyle=ConfineIn formatcopy=TRUE lockcomponents=FALSE outline -12830.16,-17167.76 -10830.16,-17167.76 -10830.16,-16167.76 -12830.16,-16167.76
RoomDefinition A11 [InComponentClass('A11')] p57: confinementstyle=ConfineIn formatcopy=TRUE lockcomponents=FALSE outline -12830.16,-17167.76 -10830.16,-17167.76 -10830.16,-16167.76 -12830.16,-16167.76
RoomDefinition A10 [InComponentClass('A10')] p58: confinementstyle=ConfineIn formatcopy=TRUE lockcomponents=FALSE outline -12830.16,-17167.76 -10830.16,-17167.76 -10830.16,-16167.76 -12830.16,-16167.76
RoomDefinition A9 [InComponentClass('A9')] p59: confinementstyle=ConfineIn formatcopy=TRUE lockcomponents=FALSE outline -12830.16,-17167.76 -10830.16,-17167.76 -10830.16,-16167.76 -12830.16,-16167.76
RoomDefinition A8 [InComponentClass('A8')] p60: confinementstyle=ConfineIn formatcopy=TRUE lockcomponents=FALSE outline -12830.16,-17167.76 -10830.16,-17167.76 -10830.16,-16167.76 -12830.16,-16167.76
RoomDefinition A7 [InComponentClass('A7')] p61: confinementstyle=ConfineIn formatcopy=TRUE lockcomponents=FALSE outline -12830.16,-17167.76 -10830.16,-17167.76 -10830.16,-16167.76 -12830.16,-16167.76
RoomDefinition A6 [InComponentClass('A6')] p62: confinementstyle=ConfineIn formatcopy=TRUE lockcomponents=FALSE outline -12830.16,-17167.76 -10830.16,-17167.76 -10830.16,-16167.76 -12830.16,-16167.76
RoomDefinition A5 [InComponentClass('A5')] p63: confinementstyle=ConfineIn formatcopy=TRUE lockcomponents=FALSE outline -12830.16,-17167.76 -10830.16,-17167.76 -10830.16,-16167.76 -12830.16,-16167.76
RoomDefinition A4 [InComponentClass('A4')] p64: confinementstyle=ConfineIn formatcopy=TRUE lockcomponents=FALSE outline -12830.16,-17167.76 -10830.16,-17167.76 -10830.16,-16167.76 -12830.16,-16167.76
RoomDefinition A3 [InComponentClass('A3')] p65: confinementstyle=ConfineIn formatcopy=TRUE lockcomponents=FALSE outline -12830.16,-17167.76 -10830.16,-17167.76 -10830.16,-16167.76 -12830.16,-16167.76
RoomDefinition A2 [InComponentClass('A2')] p66: confinementstyle=ConfineIn formatcopy=TRUE lockcomponents=FALSE outline -12830.16,-17167.76 -10830.16,-17167.76 -10830.16,-16167.76 -12830.16,-16167.76
RoomDefinition A1 [InComponentClass('A1')] p67: confinementstyle=ConfineIn formatcopy=TRUE lockcomponents=FALSE outline -12830.16,-17167.76 -10830.16,-17167.76 -10830.16,-16167.76 -12830.16,-16167.76
RoutingVias [All] p1: holewidth=11.81 width=25.59 viastyle="Through Hole" minholewidth=11.81 minwidth=25.59 maxholewidth=39.37 maxwidth=59.06
SilkToSilkClearance [All] p1: silktosilkclearance=5
SilkToSolderMaskClearance SilkscreenOverComponentPads [IsPad] p1: minsilkscreentomaskgap=5 clearancetoexposedcopper=TRUE
SolderMaskExpansion [All] p1: expansion=2
Width Width_Logo [HasFootprint('ITECH_LOGO')] p1: maxlimit=10 minlimit=1 preferedwidth=2
Width [All] p2: maxlimit=150 minlimit=3.94 preferedwidth=8 minimp=50.000000 maximp=50.000000 favimp=50.000000
18 further rules are at their usual default settings.

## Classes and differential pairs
net class RF: NetA1_C13_1 NetA1_C13_2 NetA1_Cin_1_2 NetA2_C13_1 NetA2_C13_2 NetA2_Cin_1_2 NetA3_C13_1 NetA3_C13_2 NetA3_Cin_1_2 NetA4_C13_1 NetA4_C13_2 NetA4_Cin_1_2 NetA5_C13_1 NetA5_C13_2 NetA5_Cin_1_2 NetA6_C13_1 NetA6_C13_2 NetA6_Cin_1_2 NetA7_C13_1 NetA7_C13_2 NetA7_Cin_1_2 NetA8_C13_1 NetA8_C13_2 NetA8_Cin_1_2 NetA9_C13_1 NetA9_C13_2 NetA9_Cin_1_2 NetA10_C13_1 NetA10_C13_2 NetA10_Cin_1_2 NetA11_C13_1 NetA11_C13_2 NetA11_Cin_1_2 NetA12_C13_1 NetA12_C13_2 NetA12_Cin_1_2 NetA13_C13_1 NetA13_C13_2 NetA13_Cin_1_2 NetA14_C13_1 NetA14_C13_2 NetA14_Cin_1_2 NetA15_C13_1 NetA15_C13_2 NetA15_Cin_1_2 NetA16_C13_1 NetA16_C13_2 NetA16_Cin_1_2 NetA17_C13_1 NetA17_C13_2 NetA17_Cin_1_2 NetA18_C13_1 NetA18_C13_2 NetA18_Cin_1_2 NetA19_C13_1 NetA19_C13_2 NetA19_Cin_1_2 NetA20_C13_1 NetA20_C13_2 NetA20_Cin_1_2 NetA21_C13_1 NetA21_C13_2 NetA21_Cin_1_2 NetA22_C13_1 NetA22_C13_2 NetA22_Cin_1_2 NetA23_C13_1 NetA23_C13_2 NetA23_Cin_1_2 NetA24_C13_1 NetA24_C13_2 NetA24_Cin_1_2 NetA25_C13_1 NetA25_C13_2 NetA25_Cin_1_2 NetA26_C13_1 NetA26_C13_2 NetA26_Cin_1_2 NetA27_C13_1 NetA27_C13_2 NetA27_Cin_1_2 NetA28_C13_1 NetA28_C13_2 NetA28_Cin_1_2 NetA29_C13_1 NetA29_C13_2 NetA29_Cin_1_2 NetA30_C13_1 NetA30_C13_2 NetA30_Cin_1_2 NetA31_C13_1 NetA31_C13_2 NetA31_Cin_1_2 NetA32_C13_1 NetA32_C13_2 NetA32_Cin_1_2 NetA33_C13_1 NetA33_C13_2 NetA33_Cin_1_2 NetA34_C13_1 NetA34_C13_2 NetA34_Cin_1_2 NetA35_C13_1 NetA35_C13_2 NetA35_Cin_1_2 NetA36_C13_1 NetA36_C13_2 NetA36_Cin_1_2 NetA37_C13_1 NetA37_C13_2 NetA37_Cin_1_2 NetA38_C13_1 NetA38_C13_2 NetA38_Cin_1_2 NetA39_C13_1 NetA39_C13_2 NetA39_Cin_1_2 NetA40_C13_1 NetA40_C13_2 NetA40_Cin_1_2 NetA41_C13_1 NetA41_C13_2 NetA41_Cin_1_2 NetA42_C13_1 NetA42_C13_2 NetA42_Cin_1_2 NetA43_C13_1 NetA43_C13_2 NetA43_Cin_1_2 NetA44_C13_1 NetA44_C13_2 NetA44_Cin_1_2 NetA45_C13_1 NetA45_C13_2 NetA45_Cin_1_2 NetA46_C13_1 NetA46_C13_2 NetA46_Cin_1_2 NetA47_C13_1 NetA47_C13_2 NetA47_Cin_1_2 NetA48_C13_1 NetA48_C13_2 NetA48_Cin_1_2 NetA49_C13_1 NetA49_C13_2 NetA49_Cin_1_2 NetA50_C13_1 NetA50_C13_2 NetA50_Cin_1_2 NetA51_C13_1 NetA51_C13_2 NetA51_Cin_1_2 NetA52_C13_1 NetA52_C13_2 NetA52_Cin_1_2 NetA53_C13_1 NetA53_C13_2 NetA53_Cin_1_2 NetA54_C13_1 NetA54_C13_2 NetA54_Cin_1_2 NetA55_C13_1 NetA55_C13_2 NetA55_Cin_1_2 NetA56_C13_1 NetA56_C13_2 NetA56_Cin_1_2 NetA57_C13_1 NetA57_C13_2 NetA57_Cin_1_2 NetA58_C13_1 NetA58_C13_2 NetA58_Cin_1_2 NetA59_C13_1 NetA59_C13_2 NetA59_Cin_1_2 NetA60_C13_1 NetA60_C13_2 NetA60_Cin_1_2 NetA61_C13_1 NetA61_C13_2 NetA61_Cin_1_2 NetA62_C13_1 NetA62_C13_2 NetA62_Cin_1_2 NetA63_C13_1 NetA63_C13_2 NetA63_Cin_1_2 NetA64_C13_1 NetA64_C13_2 NetA64_Cin_1_2 RF1 RF2 RF3 RF4 RF5 RF6 RF7 RF8 RF9 RF10 RF11 RF12 RF13 RF14 RF15 RF16 RF17 RF18 RF19 RF20 RF21 RF22 RF23 RF24 RF25 RF26 RF27 RF28 RF29 RF30 RF31 RF32 RF33 RF34 RF35 RF36 RF37 RF38 RF39 RF40 RF41 RF42 RF43 RF44 RF45 RF46 RF47 RF48 RF49 RF50 RF51 RF52 RF53 RF54 RF55 RF56 RF57 RF58 RF59 RF60 RF61 RF62 RF63 RF64 RF-OUT1 RF-OUT2 RF-OUT3 RF-OUT4 RF-OUT5 RF-OUT6 RF-OUT7 RF-OUT8 RF-OUT9 RF-OUT10 RF-OUT11 RF-OUT12 RF-OUT13 RF-OUT14 RF-OUT15 RF-OUT16 RF-OUT17 RF-OUT18 RF-OUT19 RF-OUT20 RF-OUT21 RF-OUT22 RF-OUT23 RF-OUT24 RF-OUT25 RF-OUT26 RF-OUT27 RF-OUT28 RF-OUT29 RF-OUT30 RF-OUT31 RF-OUT32 RF-OUT33 RF-OUT34 RF-OUT35 RF-OUT36 RF-OUT37 RF-OUT38 RF-OUT39 RF-OUT40 RF-OUT41 RF-OUT42 RF-OUT43 RF-OUT44 RF-OUT45 RF-OUT46 RF-OUT47 RF-OUT48 RF-OUT49 RF-OUT50 RF-OUT51 RF-OUT52 RF-OUT53 RF-OUT54 RF-OUT55 RF-OUT56 RF-OUT57 RF-OUT58 RF-OUT59 RF-OUT60 RF-OUT61 RF-OUT62 RF-OUT63 RF-OUT64
component class U_IDL_15_XX_A_XRM(3): K1
net class RF[64..1]: RF1 RF2 RF3 RF4 RF5 RF6 RF7 RF8 RF9 RF10 RF11 RF12 RF13 RF14 RF15 RF16 RF17 RF18 RF19 RF20 RF21 RF22 RF23 RF24 RF25 RF26 RF27 RF28 RF29 RF30 RF31 RF32 RF33 RF34 RF35 RF36 RF37 RF38 RF39 RF40 RF41 RF42 RF43 RF44 RF45 RF46 RF47 RF48 RF49 RF50 RF51 RF52 RF53 RF54 RF55 RF56 RF57 RF58 RF59 RF60 RF61 RF62 RF63 RF64
net class RF-OUT[64..1]: RF-OUT1 RF-OUT2 RF-OUT3 RF-OUT4 RF-OUT5 RF-OUT6 RF-OUT7 RF-OUT8 RF-OUT9 RF-OUT10 RF-OUT11 RF-OUT12 RF-OUT13 RF-OUT14 RF-OUT15 RF-OUT16 RF-OUT17 RF-OUT18 RF-OUT19 RF-OUT20 RF-OUT21 RF-OUT22 RF-OUT23 RF-OUT24 RF-OUT25 RF-OUT26 RF-OUT27 RF-OUT28 RF-OUT29 RF-OUT30 RF-OUT31 RF-OUT32 RF-OUT33 RF-OUT34 RF-OUT35 RF-OUT36 RF-OUT37 RF-OUT38 RF-OUT39 RF-OUT40 RF-OUT41 RF-OUT42 RF-OUT43 RF-OUT44 RF-OUT45 RF-OUT46 RF-OUT47 RF-OUT48 RF-OUT49 RF-OUT50 RF-OUT51 RF-OUT52 RF-OUT53 RF-OUT54 RF-OUT55 RF-OUT56 RF-OUT57 RF-OUT58 RF-OUT59 RF-OUT60 RF-OUT61 RF-OUT62 RF-OUT63 RF-OUT64
component class A2: A2_C1 A2_C2 A2_C3 A2_C13 A2_Cin_1 A2_L1 A2_L2 A2_RF1 A2_Rin_1
component class A3: A3_C1 A3_C2 A3_C3 A3_C13 A3_Cin_1 A3_L1 A3_L2 A3_RF1 A3_Rin_1
component class A4: A4_C1 A4_C2 A4_C3 A4_C13 A4_Cin_1 A4_L1 A4_L2 A4_RF1 A4_Rin_1
component class A5: A5_C1 A5_C2 A5_C3 A5_C13 A5_Cin_1 A5_L1 A5_L2 A5_RF1 A5_Rin_1
component class A6: A6_C1 A6_C2 A6_C3 A6_C13 A6_Cin_1 A6_L1 A6_L2 A6_RF1 A6_Rin_1
component class A7: A7_C1 A7_C2 A7_C3 A7_C13 A7_Cin_1 A7_L1 A7_L2 A7_RF1 A7_Rin_1
component class A8: A8_C1 A8_C2 A8_C3 A8_C13 A8_Cin_1 A8_L1 A8_L2 A8_RF1 A8_Rin_1
component class A9: A9_C1 A9_C2 A9_C3 A9_C13 A9_Cin_1 A9_L1 A9_L2 A9_RF1 A9_Rin_1
component class A10: A10_C1 A10_C2 A10_C3 A10_C13 A10_Cin_1 A10_L1 A10_L2 A10_RF1 A10_Rin_1
component class A11: A11_C1 A11_C2 A11_C3 A11_C13 A11_Cin_1 A11_L1 A11_L2 A11_RF1 A11_Rin_1
component class A12: A12_C1 A12_C2 A12_C3 A12_C13 A12_Cin_1 A12_L1 A12_L2 A12_RF1 A12_Rin_1
component class A13: A13_C1 A13_C2 A13_C3 A13_C13 A13_Cin_1 A13_L1 A13_L2 A13_RF1 A13_Rin_1
component class A14: A14_C1 A14_C2 A14_C3 A14_C13 A14_Cin_1 A14_L1 A14_L2 A14_RF1 A14_Rin_1
component class A15: A15_C1 A15_C2 A15_C3 A15_C13 A15_Cin_1 A15_L1 A15_L2 A15_RF1 A15_Rin_1
component class A16: A16_C1 A16_C2 A16_C3 A16_C13 A16_Cin_1 A16_L1 A16_L2 A16_RF1 A16_Rin_1
component class A17: A17_C1 A17_C2 A17_C3 A17_C13 A17_Cin_1 A17_L1 A17_L2 A17_RF1 A17_Rin_1
component class A18: A18_C1 A18_C2 A18_C3 A18_C13 A18_Cin_1 A18_L1 A18_L2 A18_RF1 A18_Rin_1
component class A19: A19_C1 A19_C2 A19_C3 A19_C13 A19_Cin_1 A19_L1 A19_L2 A19_RF1 A19_Rin_1
component class A20: A20_C1 A20_C2 A20_C3 A20_C13 A20_Cin_1 A20_L1 A20_L2 A20_RF1 A20_Rin_1
component class A21: A21_C1 A21_C2 A21_C3 A21_C13 A21_Cin_1 A21_L1 A21_L2 A21_RF1 A21_Rin_1
component class A22: A22_C1 A22_C2 A22_C3 A22_C13 A22_Cin_1 A22_L1 A22_L2 A22_RF1 A22_Rin_1
component class A23: A23_C1 A23_C2 A23_C3 A23_C13 A23_Cin_1 A23_L1 A23_L2 A23_RF1 A23_Rin_1
component class A24: A24_C1 A24_C2 A24_C3 A24_C13 A24_Cin_1 A24_L1 A24_L2 A24_RF1 A24_Rin_1
component class A25: A25_C1 A25_C2 A25_C3 A25_C13 A25_Cin_1 A25_L1 A25_L2 A25_RF1 A25_Rin_1
component class A26: A26_C1 A26_C2 A26_C3 A26_C13 A26_Cin_1 A26_L1 A26_L2 A26_RF1 A26_Rin_1
component class A27: A27_C1 A27_C2 A27_C3 A27_C13 A27_Cin_1 A27_L1 A27_L2 A27_RF1 A27_Rin_1
component class A28: A28_C1 A28_C2 A28_C3 A28_C13 A28_Cin_1 A28_L1 A28_L2 A28_RF1 A28_Rin_1
component class A29: A29_C1 A29_C2 A29_C3 A29_C13 A29_Cin_1 A29_L1 A29_L2 A29_RF1 A29_Rin_1
component class A30: A30_C1 A30_C2 A30_C3 A30_C13 A30_Cin_1 A30_L1 A30_L2 A30_RF1 A30_Rin_1
component class A31: A31_C1 A31_C2 A31_C3 A31_C13 A31_Cin_1 A31_L1 A31_L2 A31_RF1 A31_Rin_1
component class A32: A32_C1 A32_C2 A32_C3 A32_C13 A32_Cin_1 A32_L1 A32_L2 A32_RF1 A32_Rin_1
component class A33: A33_C1 A33_C2 A33_C3 A33_C13 A33_Cin_1 A33_L1 A33_L2 A33_RF1 A33_Rin_1
component class A34: A34_C1 A34_C2 A34_C3 A34_C13 A34_Cin_1 A34_L1 A34_L2 A34_RF1 A34_Rin_1
component class A35: A35_C1 A35_C2 A35_C3 A35_C13 A35_Cin_1 A35_L1 A35_L2 A35_RF1 A35_Rin_1
component class A37: A37_C1 A37_C2 A37_C3 A37_C13 A37_Cin_1 A37_L1 A37_L2 A37_RF1 A37_Rin_1
component class A38: A38_C1 A38_C2 A38_C3 A38_C13 A38_Cin_1 A38_L1 A38_L2 A38_RF1 A38_Rin_1
component class A39: A39_C1 A39_C2 A39_C3 A39_C13 A39_Cin_1 A39_L1 A39_L2 A39_RF1 A39_Rin_1
component class A40: A40_C1 A40_C2 A40_C3 A40_C13 A40_Cin_1 A40_L1 A40_L2 A40_RF1 A40_Rin_1
component class A41: A41_C1 A41_C2 A41_C3 A41_C13 A41_Cin_1 A41_L1 A41_L2 A41_RF1 A41_Rin_1
component class A42: A42_C1 A42_C2 A42_C3 A42_C13 A42_Cin_1 A42_L1 A42_L2 A42_RF1 A42_Rin_1
component class A43: A43_C1 A43_C2 A43_C3 A43_C13 A43_Cin_1 A43_L1 A43_L2 A43_RF1 A43_Rin_1
component class A44: A44_C1 A44_C2 A44_C3 A44_C13 A44_Cin_1 A44_L1 A44_L2 A44_RF1 A44_Rin_1
component class A47: A47_C1 A47_C2 A47_C3 A47_C13 A47_Cin_1 A47_L1 A47_L2 A47_RF1 A47_Rin_1
component class A48: A48_C1 A48_C2 A48_C3 A48_C13 A48_Cin_1 A48_L1 A48_L2 A48_RF1 A48_Rin_1
component class A49: A49_C1 A49_C2 A49_C3 A49_C13 A49_Cin_1 A49_L1 A49_L2 A49_RF1 A49_Rin_1
component class A50: A50_C1 A50_C2 A50_C3 A50_C13 A50_Cin_1 A50_L1 A50_L2 A50_RF1 A50_Rin_1
component class A51: A51_C1 A51_C2 A51_C3 A51_C13 A51_Cin_1 A51_L1 A51_L2 A51_RF1 A51_Rin_1
component class A52: A52_C1 A52_C2 A52_C3 A52_C13 A52_Cin_1 A52_L1 A52_L2 A52_RF1 A52_Rin_1
component class A53: A53_C1 A53_C2 A53_C3 A53_C13 A53_Cin_1 A53_L1 A53_L2 A53_RF1 A53_Rin_1
component class A54: A54_C1 A54_C2 A54_C3 A54_C13 A54_Cin_1 A54_L1 A54_L2 A54_RF1 A54_Rin_1
component class A55: A55_C1 A55_C2 A55_C3 A55_C13 A55_Cin_1 A55_L1 A55_L2 A55_RF1 A55_Rin_1
component class A56: A56_C1 A56_C2 A56_C3 A56_C13 A56_Cin_1 A56_L1 A56_L2 A56_RF1 A56_Rin_1
component class A57: A57_C1 A57_C2 A57_C3 A57_C13 A57_Cin_1 A57_L1 A57_L2 A57_RF1 A57_Rin_1
component class A58: A58_C1 A58_C2 A58_C3 A58_C13 A58_Cin_1 A58_L1 A58_L2 A58_RF1 A58_Rin_1
component class A59: A59_C1 A59_C2 A59_C3 A59_C13 A59_Cin_1 A59_L1 A59_L2 A59_RF1 A59_Rin_1
component class A60: A60_C1 A60_C2 A60_C3 A60_C13 A60_Cin_1 A60_L1 A60_L2 A60_RF1 A60_Rin_1
component class A61: A61_C1 A61_C2 A61_C3 A61_C13 A61_Cin_1 A61_L1 A61_L2 A61_RF1 A61_Rin_1
component class A62: A62_C1 A62_C2 A62_C3 A62_C13 A62_Cin_1 A62_L1 A62_L2 A62_RF1 A62_Rin_1
component class A63: A63_C1 A63_C2 A63_C3 A63_C13 A63_Cin_1 A63_L1 A63_L2 A63_RF1 A63_Rin_1
component class A64: A64_C1 A64_C2 A64_C3 A64_C13 A64_Cin_1 A64_L1 A64_L2 A64_RF1 A64_Rin_1
channel class IDL_15_XX_A_XRM(4): Amplifier1 Amplifier2 Amplifier3 Amplifier4 Amplifier5 Amplifier6 Amplifier7 Amplifier8 Amplifier9 Amplifier10 Amplifier11 Amplifier12 Amplifier13 Amplifier14 Amplifier15 Amplifier16 Amplifier17 Amplifier18 Amplifier19 Amplifier20 Amplifier21 Amplifier22 Amplifier23 Amplifier24 Amplifier25 Amplifier26 Amplifier27 Amplifier28 Amplifier29 Amplifier30 Amplifier31 Amplifier32 Amplifier33 Amplifier34 Amplifier35 Amplifier36 Amplifier37 Amplifier38 Amplifier39 Amplifier40 Amplifier41 Amplifier42 Amplifier43 Amplifier44 Amplifier45 Amplifier46 Amplifier47 Amplifier48 Amplifier49 Amplifier50 Amplifier51 Amplifier52 Amplifier53 Amplifier54 Amplifier55 Amplifier56 Amplifier57 Amplifier58 Amplifier59 Amplifier60 Amplifier61 Amplifier62 Amplifier63 Amplifier64
component class A36: A36_C1 A36_C2 A36_C3 A36_C13 A36_Cin_1 A36_L1 A36_L2 A36_RF1 A36_Rin_1
component class A45: A45_C1 A45_C2 A45_C3 A45_C13 A45_Cin_1 A45_L1 A45_L2 A45_RF1 A45_Rin_1
component class A1: A1_C1 A1_C2 A1_C3 A1_C13 A1_Cin_1 A1_L1 A1_L2 A1_RF1 A1_Rin_1
component class A46: A46_C1 A46_C2 A46_C3 A46_C13 A46_Cin_1 A46_L1 A46_L2 A46_RF1 A46_Rin_1
component class IDL_15_XX_A_XRM-TOP(1): C4 C5 C6 C7 C8 C9 C10 C11 C12 C14 C15 C16 C17 C18 C19 C20 C21 C22 C23 C24 C25 C26 C27 C28 C29 C30 C31 C32 FID1 FID2 FID3 K2
component class U_IDL_15_XX_A_XRM-20_PIN_CONNECTOR: CONN1 CONN2 CONN3 CONN4

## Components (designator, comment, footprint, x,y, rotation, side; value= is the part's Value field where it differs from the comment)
A1_C1 "10nF" CC0402N1R 1455.36,78.25 r135 top (schematic designator C1)
A1_C2 "100nF" CC0402N1R 1488.77,111.66 r135 top (schematic designator C2)
A1_C3 "1uF" CC0603RF1R 1535.75,142.62 r135 top (schematic designator C3)
A1_C13 "10nF" CC0402N1R 1238.83,43.68 r225 top (schematic designator C13)
A1_Cin_1 "10nF" CC0402N1R 1515.13,247.6 r225 top (schematic designator Cin_1)
A1_L1 "1.5uH" LC1008CS 1336.96,75 r315 top (schematic designator L1)
A1_L2 "0.5nH" LC0402N1R 1172.71,-22.44 r225 top (schematic designator L2)
A1_RF1 "AMP-PSA4-5043+" MMM1362 1410.66,179.19 r315 top (schematic designator RF1)
A1_Rin_1 "390R" RC0402N1R 1551.32,314.41 r315 top (schematic designator Rin_1)
A2_C1 "10nF" CC0402N1R 1249.71,283.9 r135 top (schematic designator C1)
A2_C2 "100nF" CC0402N1R 1283.12,317.31 r135 top (schematic designator C2)
A2_C3 "1uF" CC0603RF1R 1330.1,348.27 r135 top (schematic designator C3)
A2_C13 "10nF" CC0402N1R 1033.18,249.33 r225 top (schematic designator C13)
A2_Cin_1 "10nF" CC0402N1R 1309.48,453.25 r225 top (schematic designator Cin_1)
A2_L1 "1.5uH" LC1008CS 1131.31,280.65 r315 top (schematic designator L1)
A2_L2 "0.5nH" LC0402N1R 967.06,183.21 r225 top (schematic designator L2)
A2_RF1 "AMP-PSA4-5043+" MMM1362 1205.01,384.84 r315 top (schematic designator RF1)
A2_Rin_1 "390R" RC0402N1R 1345.67,520.06 r315 top (schematic designator Rin_1)
A3_C1 "10nF" CC0402N1R 1043.7,489.91 r135 top (schematic designator C1)
A3_C2 "100nF" CC0402N1R 1077.11,523.32 r135 top (schematic designator C2)
A3_C3 "1uF" CC0603RF1R 1124.1,554.28 r135 top (schematic designator C3)
A3_C13 "10nF" CC0402N1R 827.17,455.34 r225 top (schematic designator C13)
A3_Cin_1 "10nF" CC0402N1R 1103.47,659.26 r225 top (schematic designator Cin_1)
A3_L1 "1.5uH" LC1008CS 925.3,486.66 r315 top (schematic designator L1)
A3_L2 "0.5nH" LC0402N1R 761.06,389.22 r225 top (schematic designator L2)
A3_RF1 "AMP-PSA4-5043+" MMM1362 999,590.85 r315 top (schematic designator RF1)
A3_Rin_1 "390R" RC0402N1R 1139.66,726.07 r315 top (schematic designator Rin_1)
A4_C1 "10nF" CC0402N1R 837.7,695.92 r135 top (schematic designator C1)
A4_C2 "100nF" CC0402N1R 871.1,729.33 r135 top (schematic designator C2)
A4_C3 "1uF" CC0603RF1R 918.09,760.29 r135 top (schematic designator C3)
A4_C13 "10nF" CC0402N1R 621.16,661.34 r225 top (schematic designator C13)
A4_Cin_1 "10nF" CC0402N1R 897.47,865.26 r225 top (schematic designator Cin_1)
A4_L1 "1.5uH" LC1008CS 719.3,692.66 r315 top (schematic designator L1)
A4_L2 "0.5nH" LC0402N1R 555.05,595.23 r225 top (schematic designator L2)
A4_RF1 "AMP-PSA4-5043+" MMM1362 793,796.86 r315 top (schematic designator RF1)
A4_Rin_1 "390R" RC0402N1R 933.66,932.08 r315 top (schematic designator Rin_1)
A5_C1 "10nF" CC0402N1R 727.67,1950.05 r45 top (schematic designator C1)
A5_C2 "100nF" CC0402N1R 761.08,1916.65 r45 top (schematic designator C2)
A5_C3 "1uF" CC0603RF1R 792.04,1869.66 r45 top (schematic designator C3)
A5_C13 "10nF" CC0402N1R 693.1,2166.59 r135 top (schematic designator C13)
A5_Cin_1 "10nF" CC0402N1R 897.02,1890.28 r135 top (schematic designator Cin_1)
A5_L1 "1.5uH" LC1008CS 724.41,2068.45 r225 top (schematic designator L1)
A5_L2 "0.5nH" LC0402N1R 626.98,2232.7 r135 top (schematic designator L2)
A5_RF1 "AMP-PSA4-5043+" MMM1362 828.61,1994.75 r225 top (schematic designator RF1)
A5_Rin_1 "390R" RC0402N1R 963.83,1854.09 r225 top (schematic designator Rin_1)
A6_C1 "10nF" CC0402N1R 933.68,2156.06 r45 top (schematic designator C1)
A6_C2 "100nF" CC0402N1R 967.09,2122.66 r45 top (schematic designator C2)
A6_C3 "1uF" CC0603RF1R 998.05,2075.67 r45 top (schematic designator C3)
A6_C13 "10nF" CC0402N1R 899.1,2372.59 r135 top (schematic designator C13)
A6_Cin_1 "10nF" CC0402N1R 1103.02,2096.29 r135 top (schematic designator Cin_1)
A6_L1 "1.5uH" LC1008CS 930.42,2274.46 r225 top (schematic designator L1)
A6_L2 "0.5nH" LC0402N1R 832.99,2438.71 r135 top (schematic designator L2)
A6_RF1 "AMP-PSA4-5043+" MMM1362 1034.62,2200.76 r225 top (schematic designator RF1)
A6_Rin_1 "390R" RC0402N1R 1169.84,2060.1 r225 top (schematic designator Rin_1)
A7_C1 "10nF" CC0402N1R 1139.69,2362.07 r45 top (schematic designator C1)
A7_C2 "100nF" CC0402N1R 1173.09,2328.66 r45 top (schematic designator C2)
A7_C3 "1uF" CC0603RF1R 1204.06,2281.68 r45 top (schematic designator C3)
A7_C13 "10nF" CC0402N1R 1105.11,2578.6 r135 top (schematic designator C13)
A7_Cin_1 "10nF" CC0402N1R 1309.03,2302.3 r135 top (schematic designator Cin_1)
A7_L1 "1.5uH" LC1008CS 1136.43,2480.47 r225 top (schematic designator L1)
A7_L2 "0.5nH" LC0402N1R 1043.25,2648.89 r135 top (schematic designator L2)
A7_RF1 "AMP-PSA4-5043+" MMM1362 1240.62,2406.77 r225 top (schematic designator RF1)
A7_Rin_1 "390R" RC0402N1R 1375.84,2266.11 r225 top (schematic designator Rin_1)
A8_C1 "10nF" CC0402N1R 1345.69,2568.08 r45 top (schematic designator C1)
A8_C2 "100nF" CC0402N1R 1379.1,2534.67 r45 top (schematic designator C2)
A8_C3 "1uF" CC0603RF1R 1410.06,2487.68 r45 top (schematic designator C3)
A8_C13 "10nF" CC0402N1R 1311.12,2784.61 r135 top (schematic designator C13)
A8_Cin_1 "10nF" CC0402N1R 1515.04,2508.31 r135 top (schematic designator Cin_1)
A8_L1 "1.5uH" LC1008CS 1342.44,2686.48 r225 top (schematic designator L1)
A8_L2 "0.5nH" LC0402N1R 1245,2850.73 r135 top (schematic designator L2)
A8_RF1 "AMP-PSA4-5043+" MMM1362 1446.63,2612.78 r225 top (schematic designator RF1)
A8_Rin_1 "390R" RC0402N1R 1581.85,2472.12 r225 top (schematic designator Rin_1)
A9_C1 "10nF" CC0402N1R 1457.75,2685.7 r225 bottom (schematic designator C1)
A9_C2 "100nF" CC0402N1R 1493.94,2649.51 r225 bottom (schematic designator C2)
A9_C3 "1uF" CC0603RF1R 1540.91,2618.53 r225 bottom (schematic designator C3)
A9_C13 "10nF" CC0402N1R 1238.74,2712.23 r135 bottom (schematic designator C13)
A9_Cin_1 "10nF" CC0402N1R 1515.04,2508.31 r135 bottom (schematic designator Cin_1)
A9_L1 "1.5uH" LC1008CS 1336.87,2680.91 r45 bottom (schematic designator L1)
A9_L2 "0.5nH" LC0402N1R 1172.62,2778.34 r135 bottom (schematic designator L2)
A9_RF1 "AMP-PSA4-5043+" MMM1362 1410.57,2576.71 r45 bottom (schematic designator RF1)
A9_Rin_1 "390R" RC0402N1R 1551.23,2441.49 r45 bottom (schematic designator Rin_1)
A10_C1 "10nF" CC0402N1R 1251.74,2479.69 r225 bottom (schematic designator C1)
A10_C2 "100nF" CC0402N1R 1287.93,2443.5 r225 bottom (schematic designator C2)
A10_C3 "1uF" CC0603RF1R 1334.9,2412.52 r225 bottom (schematic designator C3)
A10_C13 "10nF" CC0402N1R 1032.73,2506.22 r135 bottom (schematic designator C13)
A10_Cin_1 "10nF" CC0402N1R 1309.03,2302.3 r135 bottom (schematic designator Cin_1)
A10_L1 "1.5uH" LC1008CS 1130.86,2474.9 r45 bottom (schematic designator L1)
A10_L2 "0.5nH" LC0402N1R 970.87,2576.51 r135 bottom (schematic designator L2)
A10_RF1 "AMP-PSA4-5043+" MMM1362 1204.56,2370.71 r45 bottom (schematic designator RF1)
A10_Rin_1 "390R" RC0402N1R 1345.22,2235.49 r45 bottom (schematic designator Rin_1)
A11_C1 "10nF" CC0402N1R 1045.73,2273.68 r225 bottom (schematic designator C1)
A11_C2 "100nF" CC0402N1R 1081.92,2237.49 r225 bottom (schematic designator C2)
A11_C3 "1uF" CC0603RF1R 1128.89,2206.51 r225 bottom (schematic designator C3)
A11_C13 "10nF" CC0402N1R 826.72,2300.21 r135 bottom (schematic designator C13)
A11_Cin_1 "10nF" CC0402N1R 1103.02,2096.29 r135 bottom (schematic designator Cin_1)
A11_L1 "1.5uH" LC1008CS 924.85,2268.89 r45 bottom (schematic designator L1)
A11_L2 "0.5nH" LC0402N1R 760.61,2366.33 r135 bottom (schematic designator L2)
A11_RF1 "AMP-PSA4-5043+" MMM1362 998.55,2164.7 r45 bottom (schematic designator RF1)
A11_Rin_1 "390R" RC0402N1R 1139.21,2029.48 r45 bottom (schematic designator Rin_1)
A12_C1 "10nF" CC0402N1R 839.72,2067.67 r225 bottom (schematic designator C1)
A12_C2 "100nF" CC0402N1R 875.91,2031.48 r225 bottom (schematic designator C2)
A12_C3 "1uF" CC0603RF1R 922.88,2000.5 r225 bottom (schematic designator C3)
A12_C13 "10nF" CC0402N1R 620.71,2094.2 r135 bottom (schematic designator C13)
A12_Cin_1 "10nF" CC0402N1R 897.02,1890.28 r135 bottom (schematic designator Cin_1)
A12_L1 "1.5uH" LC1008CS 718.85,2062.89 r45 bottom (schematic designator L1)
A12_L2 "0.5nH" LC0402N1R 554.6,2160.32 r135 bottom (schematic designator L2)
A12_RF1 "AMP-PSA4-5043+" MMM1362 792.55,1958.69 r45 bottom (schematic designator RF1)
A12_Rin_1 "390R" RC0402N1R 933.21,1823.47 r45 bottom (schematic designator Rin_1)
A13_C1 "10nF" CC0402N1R 720.08,807.97 r315 bottom (schematic designator C1)
A13_C2 "100nF" CC0402N1R 756.27,844.16 r315 bottom (schematic designator C2)
A13_C3 "1uF" CC0603RF1R 787.25,891.13 r315 bottom (schematic designator C3)
A13_C13 "10nF" CC0402N1R 693.55,588.96 r225 bottom (schematic designator C13)
A13_Cin_1 "10nF" CC0402N1R 897.47,865.26 r225 bottom (schematic designator Cin_1)
A13_L1 "1.5uH" LC1008CS 724.86,687.1 r135 bottom (schematic designator L1)
A13_L2 "0.5nH" LC0402N1R 627.43,522.85 r225 bottom (schematic designator L2)
A13_RF1 "AMP-PSA4-5043+" MMM1362 829.06,760.8 r135 bottom (schematic designator RF1)
A13_Rin_1 "390R" RC0402N1R 964.28,901.45 r135 bottom (schematic designator Rin_1)
A14_C1 "10nF" CC0402N1R 926.08,601.96 r315 bottom (schematic designator C1)
A14_C2 "100nF" CC0402N1R 962.27,638.15 r315 bottom (schematic designator C2)
A14_C3 "1uF" CC0603RF1R 993.25,685.12 r315 bottom (schematic designator C3)
A14_C13 "10nF" CC0402N1R 899.55,382.96 r225 bottom (schematic designator C13)
A14_Cin_1 "10nF" CC0402N1R 1103.47,659.26 r225 bottom (schematic designator Cin_1)
A14_L1 "1.5uH" LC1008CS 930.87,481.09 r135 bottom (schematic designator L1)
A14_L2 "0.5nH" LC0402N1R 833.44,316.84 r225 bottom (schematic designator L2)
A14_RF1 "AMP-PSA4-5043+" MMM1362 1035.07,554.79 r135 bottom (schematic designator RF1)
A14_Rin_1 "390R" RC0402N1R 1170.29,695.45 r135 bottom (schematic designator Rin_1)
A15_C1 "10nF" CC0402N1R 1132.09,395.96 r315 bottom (schematic designator C1)
A15_C2 "100nF" CC0402N1R 1168.28,432.15 r315 bottom (schematic designator C2)
A15_C3 "1uF" CC0603RF1R 1199.26,479.12 r315 bottom (schematic designator C3)
A15_C13 "10nF" CC0402N1R 1105.56,176.95 r225 bottom (schematic designator C13)
A15_Cin_1 "10nF" CC0402N1R 1309.48,453.25 r225 bottom (schematic designator Cin_1)
A15_L1 "1.5uH" LC1008CS 1136.88,275.08 r135 bottom (schematic designator L1)
A15_L2 "0.5nH" LC0402N1R 1039.44,110.83 r225 bottom (schematic designator L2)
A15_RF1 "AMP-PSA4-5043+" MMM1362 1241.07,348.78 r135 bottom (schematic designator RF1)
A15_Rin_1 "390R" RC0402N1R 1376.29,489.44 r135 bottom (schematic designator Rin_1)
A16_C1 "10nF" CC0402N1R 1337.74,190.31 r315 bottom (schematic designator C1)
A16_C2 "100nF" CC0402N1R 1373.93,226.5 r315 bottom (schematic designator C2)
A16_C3 "1uF" CC0603RF1R 1404.91,273.47 r315 bottom (schematic designator C3)
A16_C13 "10nF" CC0402N1R 1311.21,-28.7 r225 bottom (schematic designator C13)
A16_Cin_1 "10nF" CC0402N1R 1515.13,247.6 r225 bottom (schematic designator Cin_1)
A16_L1 "1.5uH" LC1008CS 1342.53,69.43 r135 bottom (schematic designator L1)
A16_L2 "0.5nH" LC0402N1R 1245.09,-94.82 r225 bottom (schematic designator L2)
A16_RF1 "AMP-PSA4-5043+" MMM1362 1446.73,143.13 r135 bottom (schematic designator RF1)
A16_Rin_1 "390R" RC0402N1R 1581.94,283.79 r135 bottom (schematic designator Rin_1)
A17_C1 "10nF" CC0402N1R 4159.18,2771.44 r135 bottom (schematic designator C1)
A17_C2 "100nF" CC0402N1R 4122.99,2735.25 r135 bottom (schematic designator C2)
A17_C3 "1uF" CC0603RF1R 4092.01,2688.28 r135 bottom (schematic designator C3)
A17_C13 "10nF" CC0402N1R 4185.71,2990.45 r45 bottom (schematic designator C13)
A17_Cin_1 "10nF" CC0402N1R 3981.79,2714.15 r45 bottom (schematic designator Cin_1)
A17_L1 "1.5uH" LC1008CS 4154.39,2892.32 r315 bottom (schematic designator L1)
A17_L2 "0.5nH" LC0402N1R 4251.83,3056.57 r45 bottom (schematic designator L2)
A17_RF1 "AMP-PSA4-5043+" MMM1362 4050.19,2818.62 r315 bottom (schematic designator RF1)
A17_Rin_1 "390R" RC0402N1R 3914.98,2677.96 r315 bottom (schematic designator Rin_1)
A18_C1 "10nF" CC0402N1R 3953.17,2977.45 r135 bottom (schematic designator C1)
A18_C2 "100nF" CC0402N1R 3916.98,2941.26 r135 bottom (schematic designator C2)
A18_C3 "1uF" CC0603RF1R 3886,2894.29 r135 bottom (schematic designator C3)
A18_C13 "10nF" CC0402N1R 3979.7,3196.46 r45 bottom (schematic designator C13)
A18_Cin_1 "10nF" CC0402N1R 3775.78,2920.16 r45 bottom (schematic designator Cin_1)
A18_L1 "1.5uH" LC1008CS 3948.38,3098.33 r315 bottom (schematic designator L1)
A18_L2 "0.5nH" LC0402N1R 4045.82,3262.58 r45 bottom (schematic designator L2)
A18_RF1 "AMP-PSA4-5043+" MMM1362 3844.19,3024.63 r315 bottom (schematic designator RF1)
A18_Rin_1 "390R" RC0402N1R 3708.97,2883.97 r315 bottom (schematic designator Rin_1)
A19_C1 "10nF" CC0402N1R 3747.16,3183.46 r135 bottom (schematic designator C1)
A19_C2 "100nF" CC0402N1R 3710.97,3147.27 r135 bottom (schematic designator C2)
A19_C3 "1uF" CC0603RF1R 3679.99,3100.3 r135 bottom (schematic designator C3)
A19_C13 "10nF" CC0402N1R 3773.69,3402.47 r45 bottom (schematic designator C13)
A19_Cin_1 "10nF" CC0402N1R 3569.77,3126.17 r45 bottom (schematic designator Cin_1)
A19_L1 "1.5uH" LC1008CS 3742.37,3304.33 r315 bottom (schematic designator L1)
A19_L2 "0.5nH" LC0402N1R 3839.81,3468.58 r45 bottom (schematic designator L2)
A19_RF1 "AMP-PSA4-5043+" MMM1362 3638.18,3230.63 r315 bottom (schematic designator RF1)
A19_Rin_1 "390R" RC0402N1R 3502.96,3089.97 r315 bottom (schematic designator Rin_1)
A20_C1 "10nF" CC0402N1R 3541.16,3389.46 r135 bottom (schematic designator C1)
A20_C2 "100nF" CC0402N1R 3504.97,3353.27 r135 bottom (schematic designator C2)
A20_C3 "1uF" CC0603RF1R 3473.99,3306.3 r135 bottom (schematic designator C3)
A20_C13 "10nF" CC0402N1R 3567.69,3608.47 r45 bottom (schematic designator C13)
A20_Cin_1 "10nF" CC0402N1R 3363.77,3332.17 r45 bottom (schematic designator Cin_1)
A20_L1 "1.5uH" LC1008CS 3536.37,3510.34 r315 bottom (schematic designator L1)
A20_L2 "0.5nH" LC0402N1R 3633.8,3674.59 r45 bottom (schematic designator L2)
A20_RF1 "AMP-PSA4-5043+" MMM1362 3432.17,3436.64 r315 bottom (schematic designator RF1)
A20_Rin_1 "390R" RC0402N1R 3296.95,3295.98 r315 bottom (schematic designator Rin_1)
A21_C1 "10nF" CC0402N1R 2281.81,3509.76 r225 bottom (schematic designator C1)
A21_C2 "100nF" CC0402N1R 2318,3473.57 r225 bottom (schematic designator C2)
A21_C3 "1uF" CC0603RF1R 2364.97,3442.59 r225 bottom (schematic designator C3)
A21_C13 "10nF" CC0402N1R 2062.8,3536.29 r135 bottom (schematic designator C13)
A21_Cin_1 "10nF" CC0402N1R 2339.1,3332.37 r135 bottom (schematic designator Cin_1)
A21_L1 "1.5uH" LC1008CS 2160.93,3504.97 r45 bottom (schematic designator L1)
A21_L2 "0.5nH" LC0402N1R 1996.68,3602.41 r135 bottom (schematic designator L2)
A21_RF1 "AMP-PSA4-5043+" MMM1362 2234.63,3400.78 r45 bottom (schematic designator RF1)
A21_Rin_1 "390R" RC0402N1R 2375.29,3265.56 r45 bottom (schematic designator Rin_1)
A22_C1 "10nF" CC0402N1R 2075.8,3303.75 r225 bottom (schematic designator C1)
A22_C2 "100nF" CC0402N1R 2111.99,3267.56 r225 bottom (schematic designator C2)
A22_C3 "1uF" CC0603RF1R 2158.96,3236.58 r225 bottom (schematic designator C3)
A22_C13 "10nF" CC0402N1R 1856.79,3330.28 r135 bottom (schematic designator C13)
A22_Cin_1 "10nF" CC0402N1R 2133.09,3126.36 r135 bottom (schematic designator Cin_1)
A22_L1 "1.5uH" LC1008CS 1954.93,3298.96 r45 bottom (schematic designator L1)
A22_L2 "0.5nH" LC0402N1R 1790.68,3396.4 r135 bottom (schematic designator L2)
A22_RF1 "AMP-PSA4-5043+" MMM1362 2028.63,3194.77 r45 bottom (schematic designator RF1)
A22_Rin_1 "390R" RC0402N1R 2169.28,3059.55 r45 bottom (schematic designator Rin_1)
A23_C1 "10nF" CC0402N1R 1869.79,3097.75 r225 bottom (schematic designator C1)
A23_C2 "100nF" CC0402N1R 1905.98,3061.55 r225 bottom (schematic designator C2)
A23_C3 "1uF" CC0603RF1R 1952.95,3030.58 r225 bottom (schematic designator C3)
A23_C13 "10nF" CC0402N1R 1650.79,3124.28 r135 bottom (schematic designator C13)
A23_Cin_1 "10nF" CC0402N1R 1927.09,2920.36 r135 bottom (schematic designator Cin_1)
A23_L1 "1.5uH" LC1008CS 1748.92,3092.96 r45 bottom (schematic designator L1)
A23_L2 "0.5nH" LC0402N1R 1584.67,3190.39 r135 bottom (schematic designator L2)
A23_RF1 "AMP-PSA4-5043+" MMM1362 1822.62,2988.76 r45 bottom (schematic designator RF1)
A23_Rin_1 "390R" RC0402N1R 1963.28,2853.54 r45 bottom (schematic designator Rin_1)
A24_C1 "10nF" CC0402N1R 1663.79,2891.74 r225 bottom (schematic designator C1)
A24_C2 "100nF" CC0402N1R 1699.98,2855.55 r225 bottom (schematic designator C2)
A24_C3 "1uF" CC0603RF1R 1746.95,2824.57 r225 bottom (schematic designator C3)
A24_C13 "10nF" CC0402N1R 1444.78,2918.27 r135 bottom (schematic designator C13)
A24_Cin_1 "10nF" CC0402N1R 1721.08,2714.35 r135 bottom (schematic designator Cin_1)
A24_L1 "1.5uH" LC1008CS 1542.91,2886.95 r45 bottom (schematic designator L1)
A24_L2 "0.5nH" LC0402N1R 1378.66,2984.39 r135 bottom (schematic designator L2)
A24_RF1 "AMP-PSA4-5043+" MMM1362 1616.61,2782.75 r45 bottom (schematic designator RF1)
A24_Rin_1 "390R" RC0402N1R 1757.27,2647.54 r45 bottom (schematic designator Rin_1)
A25_C1 "10nF" CC0402N1R 1551.74,2774.12 r45 top (schematic designator C1)
A25_C2 "100nF" CC0402N1R 1585.14,2740.71 r45 top (schematic designator C2)
A25_C3 "1uF" CC0603RF1R 1616.1,2693.73 r45 top (schematic designator C3)
A25_C13 "10nF" CC0402N1R 1517.16,2990.65 r135 top (schematic designator C13)
A25_Cin_1 "10nF" CC0402N1R 1721.08,2714.35 r135 top (schematic designator Cin_1)
A25_L1 "1.5uH" LC1008CS 1548.48,2892.52 r225 top (schematic designator L1)
A25_L2 "0.5nH" LC0402N1R 1451.04,3056.77 r135 top (schematic designator L2)
A25_RF1 "AMP-PSA4-5043+" MMM1362 1652.67,2818.82 r225 top (schematic designator RF1)
A25_Rin_1 "390R" RC0402N1R 1787.89,2678.16 r225 top (schematic designator Rin_1)
A26_C1 "10nF" CC0402N1R 1757.74,2980.13 r45 top (schematic designator C1)
A26_C2 "100nF" CC0402N1R 1791.15,2946.72 r45 top (schematic designator C2)
A26_C3 "1uF" CC0603RF1R 1822.11,2899.73 r45 top (schematic designator C3)
A26_C13 "10nF" CC0402N1R 1723.17,3196.66 r135 top (schematic designator C13)
A26_Cin_1 "10nF" CC0402N1R 1927.09,2920.36 r135 top (schematic designator Cin_1)
A26_L1 "1.5uH" LC1008CS 1754.49,3098.52 r225 top (schematic designator L1)
A26_L2 "0.5nH" LC0402N1R 1657.05,3262.77 r135 top (schematic designator L2)
A26_RF1 "AMP-PSA4-5043+" MMM1362 1858.68,3024.82 r225 top (schematic designator RF1)
A26_Rin_1 "390R" RC0402N1R 1993.9,2884.17 r225 top (schematic designator Rin_1)
A27_C1 "10nF" CC0402N1R 1963.75,3186.13 r45 top (schematic designator C1)
A27_C2 "100nF" CC0402N1R 1997.16,3152.73 r45 top (schematic designator C2)
A27_C3 "1uF" CC0603RF1R 2028.12,3105.74 r45 top (schematic designator C3)
A27_C13 "10nF" CC0402N1R 1929.17,3402.66 r135 top (schematic designator C13)
A27_Cin_1 "10nF" CC0402N1R 2133.09,3126.36 r135 top (schematic designator Cin_1)
A27_L1 "1.5uH" LC1008CS 1960.49,3304.53 r225 top (schematic designator L1)
A27_L2 "0.5nH" LC0402N1R 1863.06,3468.78 r135 top (schematic designator L2)
A27_RF1 "AMP-PSA4-5043+" MMM1362 2064.69,3230.83 r225 top (schematic designator RF1)
A27_Rin_1 "390R" RC0402N1R 2199.91,3090.17 r225 top (schematic designator Rin_1)
A28_C1 "10nF" CC0402N1R 2169.76,3392.14 r45 top (schematic designator C1)
A28_C2 "100nF" CC0402N1R 2203.16,3358.73 r45 top (schematic designator C2)
A28_C3 "1uF" CC0603RF1R 2234.13,3311.75 r45 top (schematic designator C3)
A28_C13 "10nF" CC0402N1R 2135.18,3608.67 r135 top (schematic designator C13)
